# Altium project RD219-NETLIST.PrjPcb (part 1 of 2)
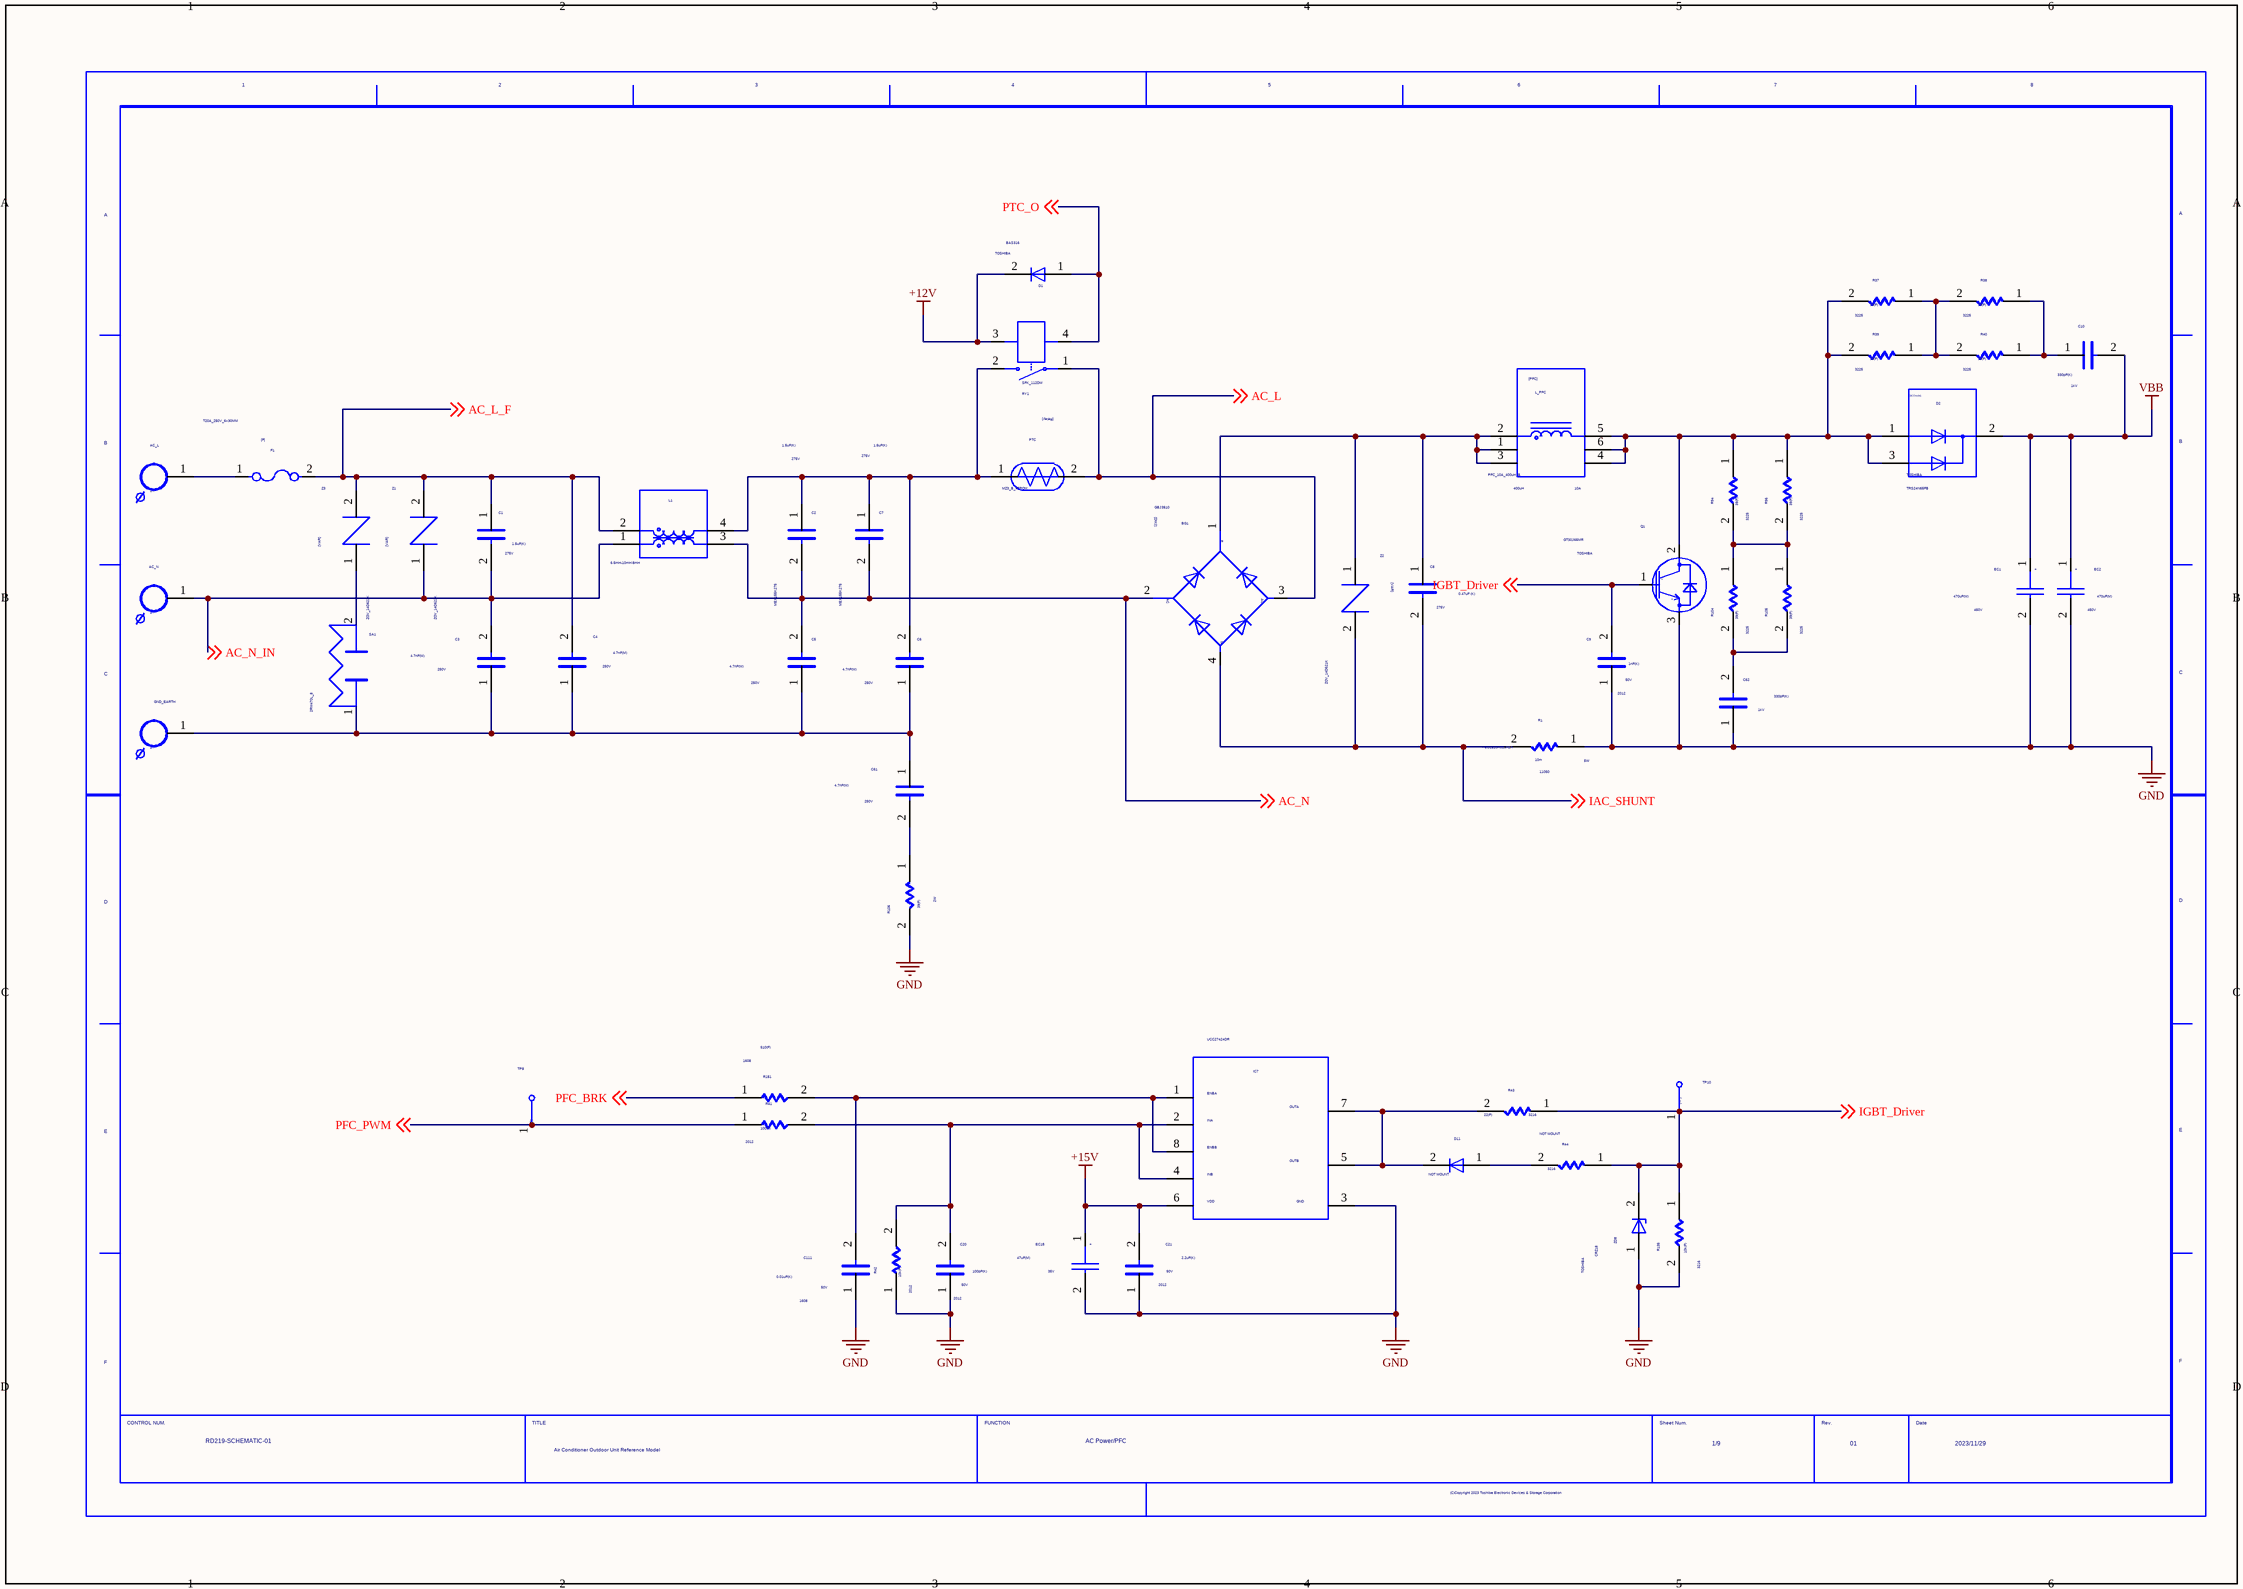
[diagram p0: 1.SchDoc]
9 sheets, 407 parts. Net scope: global (net labels, ports and power ports of the same name join across sheets).
Sheets:
  1.SchDoc
  2.SchDoc
  3.SchDoc
  4.SchDoc
  5.SchDoc
  6.SchDoc
  7.SchDoc
  8.SchDoc
  9.SchDoc

## Sheet 1.SchDoc
size 420 x 297 mm

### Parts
(Parts that share a designator on the sheet are numbered #1, #2 ... from top to bottom, then left to right.)
AC_L  TB1Y  (value not drawn)
AC_N  TB1Y  (value not drawn)
BG1  VAL1: GBJ3510  (hidden comment: DMJ)
C1  VAL2: 275V  VAL1: 1.5uF(K)  (hidden comment: C)
C2  VAL2: 275V  VAL1: 1.5uF(K)  VAL3: MEX155K275  (hidden comment: C)
C3  VAL2: 250V  VAL1: 4.7nF(M)  (hidden comment: C)
C4  VAL2: 250V  VAL1: 4.7nF(M)  (hidden comment: C)
C5  VAL2: 250V  VAL1: 4.7nF(M)  (hidden comment: C)
C6  VAL2: 250V  VAL1: 4.7nF(M)  (hidden comment: C)
C7  VAL2: 275V  VAL1: 1.5uF(K)  VAL3: MEX155K275  (hidden comment: C)
C8  VAL2: 275V  VAL1: 0.47uF (K)  (hidden comment: C)
C9  SIZECODESMD: 2012  VAL2: 50V  VAL1: 1nF(K)  (hidden comment: C)
C10  VAL2: 1kV  VAL1: 330pF(K)  (hidden comment: C)
C20  SIZECODESMD: 2012  VAL2: 50V  VAL1: 100pF(K)  (hidden comment: C)
C21  SIZECODESMD: 2012  VAL2: 50V  VAL1: 2.2uF(K)  (hidden comment: C)
C61  VAL2: 250V  VAL1: 4.7nF(M)  (hidden comment: C)
C62  VAL2: 1kV  VAL1: 330pF(K)  (hidden comment: C)
C111  SIZECODESMD: 1608  VAL2: 50V  VAL1: 0.01uF(K)  (hidden comment: C)
D1  USERCOMPTEXT3: TOSHIBA  VAL3: BAS316  (hidden comment: D_CUSTOM)
D2  USERCOMPTEXT3: TOSHIBA  VAL3: TRS24N65FB  (hidden comment: TRS24N)
D11  NOTMOUNT: NOT MOUNT  (hidden comment: D_CUSTOM)
EC1  VAL2: 450V  VAL1: 470uF(M)  (hidden comment: EC)
EC2  VAL2: 450V  VAL1: 470uF(M)  (hidden comment: EC)
EC15  VAL2: 35V  VAL1: 47uF(M)  (hidden comment: EC)
F1  COMP: T20A_250V_6x30MM  (hidden comment: F)
GND_EARTH  TB1Y  (value not drawn)
IC7  VAL1: UCC27424DR  (hidden comment: UCC27424)
L1  COMPCOMMENT: 6.5mH-10mH:8mH  (hidden comment: L2Y)
L_PFC  VAL3: PFC_10A_400uH_B  VAL2: 10A  VAL1: 400uH  (hidden comment: PFC)
PTC  VAL1: MZ3_B_47ROM  (hidden comment: PTC)
Q1  USERCOMPTEXT3: TOSHIBA  VAL3: GT30J65MR  (hidden comment: IGBT)
R1  SIZECODESMD: 11050  VAL3: FCSL110R010FER  VAL2: 5W  VAL1: 10m  (hidden comment: R)
R37  SIZECODESMD: 3225  VAL1: 39(F)  (hidden comment: R)
R38  SIZECODESMD: 3225  VAL1: 39(F)  (hidden comment: R)
R39  SIZECODESMD: 3225  VAL1: 39(F)  (hidden comment: R)
R40  SIZECODESMD: 3225  VAL1: 39(F)  (hidden comment: R)
R41  SIZECODESMD: 2012  VAL1: 100(F)  (hidden comment: R)
R42  SIZECODESMD: 2012  VAL1: 10k(F)  (hidden comment: R)
R43  SIZECODESMD: 3216  VAL1: 22(F)  (hidden comment: R)
R44  SIZECODESMD: 3216  NOTMOUNT: NOT MOUNT  (hidden comment: R)
R94  SIZECODESMD: 3225  VAL1: 39(F)  (hidden comment: R)
R96  SIZECODESMD: 3225  VAL1: 39(F)  (hidden comment: R)
R104  SIZECODESMD: 3225  VAL1: 39(F)  (hidden comment: R)
R105  SIZECODESMD: 3225  VAL1: 39(F)  (hidden comment: R)
R106  VAL2: 2W  VAL1: 39(F)  (hidden comment: R)
R135  SIZECODESMD: 3216  VAL1: 10k(F)  (hidden comment: R)
R151  SIZECODESMD: 1608  VAL1: 510(F)  (hidden comment: R)
RY1  VAL1: SFK_112DM  (hidden comment: SFK-112)
SA1  COMP: 2RM470L_8  (hidden comment: GDT)
TP8  TP  (value not drawn)
TP10  TP  (value not drawn)
U?#1  DATE: 2023/11/29  TITLE: Air Conditioner Outdoor Unit / Reference Model  SHEETNUMBER: 1/9  FUNCTION: AC Power/PFC  REVISION: 01  DRAWINGNUMBER: RD219-SCHEMATIC-01  (hidden comment: WAKU_DEF100)
Z1  VAL3: ZOV_14D621K  (hidden comment: VAR)
Z2  VAL3: ZOV_14D621K  (hidden comment: VAR)
Z3  VAL3: ZOV_14D621K  (hidden comment: VAR)
ZD8  USERCOMPTEXT3: TOSHIBA  VAL1: CRZ18  (hidden comment: ZD)

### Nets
+12V: D1.2 RY1.3
+15V: C21.2 EC15.1 IC7.6
GND: C9.1 C20.1 C21.1 C62.1 C111.1 EC1.2 EC2.2 EC15.2 IC7.3 Q1.3 R1.1 R42.1 R106.2 R135.2 ZD8.1(A)
VBB: C10.2 D2.2 EC1.1 EC2.1
AC_L: BG1.3 PTC.2 RY1.1 ; off-sheet AC_L
AC_L_F: C1.1 C4.2 F1.2 L1.2 Z1.2 Z3.2 ; off-sheet AC_L_F
AC_N: BG1.2 C2.2 C5.2 C7.2 L1.3 ; off-sheet AC_N
AC_N_IN: AC_N.1 C1.2 C3.2 L1.1 Z1.1 ; off-sheet AC_N_IN
IAC_SHUNT: BG1.4 C8.2 R1.2 Z2.2 ; off-sheet IAC_SHUNT
IGBT_Driver: C9.2 Q1.1 R43.1 R44.1 R135.1 TP10.1 ZD8.2(C) ; off-sheet IGBT_Driver
NetAC_L_1: AC_L.1 F1.1
NetBG1_1: BG1.1 C8.1 L_PFC.1 L_PFC.2 L_PFC.3 Z2.1
NetC2_1: C2.1 C6.2 C7.1 L1.4 PTC.1 RY1.2
NetC3_1: C3.1 C4.1 C5.1 C6.1 C61.1 GND_EARTH.1 SA1.1
NetC10_1: C10.1 R38.1 R40.1
NetC20_2: C20.2 IC7.2 IC7.4 R41.2 R42.2
NetC61_2: C61.2 R106.1
NetC62_2: C62.2 R104.2 R105.2
NetC111_2: C111.2 IC7.1 IC7.8 R151.2
NetD2_1: D2.1 D2.3 L_PFC.4 L_PFC.5 L_PFC.6 Q1.2 R37.2 R39.2 R94.1 R96.1
NetD11_1: D11.1 R44.2
NetD11_2: D11.2 IC7.5 IC7.7 R43.2
NetR37_1: R37.1 R38.2 R39.1 R40.2
NetR94_2: R94.2 R96.2 R104.1 R105.1
NetSA1_2: SA1.2 Z3.1
PFC_BRK: R151.1 ; off-sheet PFC_BRK
PFC_PWM: R41.1 TP8.1 ; off-sheet PFC_PWM
PTC_O: D1.1 RY1.4 ; off-sheet PTC_O

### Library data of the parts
AC_L = TB1Y: SAVEAREA0: -4386,-117,16897,10471; TIME: 15:17:35; UPDATEUSER: w20165dm; SAVECOUNT: 1; OriginalSymbolOrigin: (0,7620); VAL3: AC-L; COMP: PAD
AC_N = TB1Y: SAVEAREA0: -4386,-117,16897,10471; TIME: 15:17:35; UPDATEUSER: w20165dm; SAVECOUNT: 1; OriginalSymbolOrigin: (0,7620); VAL3: AC-N; COMP: PAD
BG1 = DMJ: SAVECOUNT: 8; SAVEAREA0: -14111,-292,39054,26173; TIME: 10:09:47; UPDATEUSER: 19990028; UPDATETIME: 09:28:12; OriginalSymbolOrigin: (0,25400)
C1 = C_Dup1: OriginalSymbolOrigin: (2540,7620); VAL3: MEX155K275
C2 C7 = C_Dup1: OriginalSymbolOrigin: (2540,7620)
C3-C6 C61 = C_Dup1: OriginalSymbolOrigin: (2540,7620); VAL3: DE1E3KX472MA4BN01F; COMP: JN472M
C8 = C_Dup1: OriginalSymbolOrigin: (2540,7620); COMPCOMMENT: MKP474/275VAC; VAL3: MEX474K275
C9 = C_Dup1: OriginalSymbolOrigin: (2540,7620); VAL3: AC0805KRX7R9BB102
C10 C62 = C_Dup1: OriginalSymbolOrigin: (2540,7620); VAL3: CK45-B3AD331KYGNA; COMP: 331_1KV
C20 = C: OriginalSymbolOrigin: (2540,7620); VAL3: AC0805KRX7R9BB101
C21 = C: OriginalSymbolOrigin: (2540,7620); COMP: AC0805KRX7R9BB225
C111 = C: OriginalSymbolOrigin: (2540,7620); VAL3: GCM188R71H103KA37D
D1 = D_CUSTOM: SAVEAREA0: -1668,-97,14265,7829; SAVECOUNT: 4; TIME: 14:49:55; UPDATEUSER: w20165dm; UPDATETIME: 16:47:49; OriginalSymbolOrigin: (5080,5080)
D2 = TRS24N: SAVEAREA0: -10023,-235,32546,20943; TIME: 17:15:17; UPDATEUSER: w20165dm; SAVECOUNT: 1; OriginalSymbolOrigin: (5080,20320)
D11 = D_CUSTOM: SAVEAREA0: -1668,-97,14265,7829; SAVECOUNT: 4; TIME: 14:49:55; UPDATEUSER: w20165dm; UPDATETIME: 16:47:49; OriginalSymbolOrigin: (5080,5080); COMP: 1N4148
EC1 EC2 = EC: SAVEAREA0: -1432,-1528,20311,14389; SAVECOUNT: 53; TIME: 15:02:55; UPDATEUSER: w20165dm; UPDATETIME: 16:35:05; OriginalSymbolOrigin: (2540,10160); VAL3: 450VXG470MEFCSN35X45
EC15 = EC: SAVEAREA0: -1432,-1528,20311,14389; SAVECOUNT: 53; TIME: 15:02:55; UPDATEUSER: w20165dm; UPDATETIME: 16:35:05; OriginalSymbolOrigin: (2540,10160); VAL3: CS1V470M_CRE54
F1 = F: OriginalSymbolOrigin: (2540,5080); VAL2: 250V; VAL1: 20A
GND_EARTH = TB1Y: SAVEAREA0: -4386,-117,16897,10471; TIME: 15:17:35; UPDATEUSER: w20165dm; SAVECOUNT: 1; OriginalSymbolOrigin: (0,7620); VAL3: GND_EARTH; COMP: PAD
IC7 = UCC27424: SAVEAREA0: -18701,-404,54363,35945; TIME: 14:53:37; UPDATEUSER: w20165dm; UPDATETIME: 17:37:13; SAVECOUNT: 7; OriginalSymbolOrigin: (5080,33020)
L1 = L2Y: SAVEAREA0: -7346,-206,29901,18324; TIME: 15:13:45; UPDATEUSER: w20165dm; SAVECOUNT: 1; OriginalSymbolOrigin: (5080,15240); VAL2: 20A; VAL1: 6.5mH-10mH; COMP: INDUCTOR_IRON_DOT
L_PFC = PFC: SAVEAREA0: -15388,-294,37822,26178; TIME: 13:55:27; UPDATEUSER: w20165dm; SAVECOUNT: 1; OriginalSymbolOrigin: (5080,22860); COMPCOMMENT: Inductor Iron Dot
PTC = PTC: TIME: 17:09:47; UPDATEUSER: w20165dm; UPDATETIME: 17:16:29; SAVECOUNT: 2; SAVEAREA0: -4525,-147,22079,13088; OriginalSymbolOrigin: (5080,7620)
Q1 = IGBT: TIME: 09:39:04; UPDATEUSER: w20165dm; UPDATETIME: 16:59:47; SAVECOUNT: 10; SAVEAREA0: -8472,-176,23454,15707; OriginalSymbolOrigin: (2540,12700)
R1 = R_Dup1: OriginalSymbolOrigin: (5080,5080)
R37 R38 R40 = R_Dup1: OriginalSymbolOrigin: (5080,5080); VAL3: AC1210FR-0739RL; VAL2: 500mW; COMP: AC1210FR_0739RL
R39 = R_Dup1: OriginalSymbolOrigin: (5080,5080); VAL2: 500mW; COMP: AC1210FR_0739RL; VAL3: AC1210FR-0739RL
R41 = R: OriginalSymbolOrigin: (5080,5080); VAL3: AC0805FR-07100RL; VAL2: 125mW; COMP: AC0805FR_07100RL
R42 = R: OriginalSymbolOrigin: (5080,5080); VAL3: AC0805FR-0710KL; VAL2: 125mW; COMP: AC0805FR_0710KL
R43 = R: OriginalSymbolOrigin: (5080,5080); VAL2: 250mW; VAL3: AC1206FR-0722RL; COMP: AC1206FR_0722RL
R44 = R: OriginalSymbolOrigin: (5080,5080); COMP: SMT_1206_R
R94 R104 = R_Dup1: OriginalSymbolOrigin: (5080,5080); VAL2: 500mW; VAL3: AC1210FR_0739RL
R96 R105 = R_Dup1: OriginalSymbolOrigin: (5080,5080); VAL3: AC1210FR_0739RL; VAL2: 500mW
R106 = R_Dup1: OriginalSymbolOrigin: (5080,5080); VAL3: MFR2WSFTE73_39R
R135 = R: OriginalSymbolOrigin: (5080,5080); VAL3: AC1206FR_0710KL; VAL2: 250mW
R151 = R: OriginalSymbolOrigin: (5080,5080); VAL3: AC0603FR_07510RL; VAL2: 100mW
RY1 = SFK-112: SAVEAREA0: -13231,-231,28521,20540; TIME: 14:06:16; UPDATEUSER: w20165dm; UPDATETIME: 17:57:42; SAVECOUNT: 24; OriginalSymbolOrigin: (2540,12700)
SA1 = GDT: TIME: 16:28:26; UPDATEUSER: w20165dm; UPDATETIME: 16:32:17; SAVECOUNT: 3; SAVEAREA0: -9109,-176,22817,15707; OriginalSymbolOrigin: (0,15240); VAL3: 2RM470L-8; VAL2: 10kA; VAL1: 470V
TP8 TP10 = TP_Dup1: TIME: 16:12:21; UPDATEUSER: fukuda-y; UPDATETIME: 16:18:11; SAVECOUNT: 2; SAVEAREA0: -242,-92,12810,7836; OriginalSymbolOrigin: (0,7620); VAL3: ZXD
U?#1 = WAKU_DEF100: PLOTTIME: HH:MM; SAVEAREA0: -45080,-4508,463680,304612; TIME: 17:28:05; UPDATEUSER: sptcae13; UPDATETIME: 08:19:30; SAVECOUNT: 8; OriginalSymbolOrigin: (10160,284480)
Z1 Z3 = VAR: SAVEAREA0: -418,-1801,15408,7141; SAVECOUNT: 5; OriginalSymbolOrigin: (5080,5080)
Z2 = VAR: SAVEAREA0: -418,-1801,15408,7141; SAVECOUNT: 5; OriginalSymbolOrigin: (5080,5080); COMP: ZOV_14D621K_18MM
ZD8 = ZD: SAVEAREA0: -4071,-115,16804,10270; TIME: 09:43:08; UPDATEUSER: w20165dm; UPDATETIME: 16:32:57; SAVECOUNT: 6; OriginalSymbolOrigin: (5080,5080)

## Sheet 2.SchDoc
size 420 x 297 mm
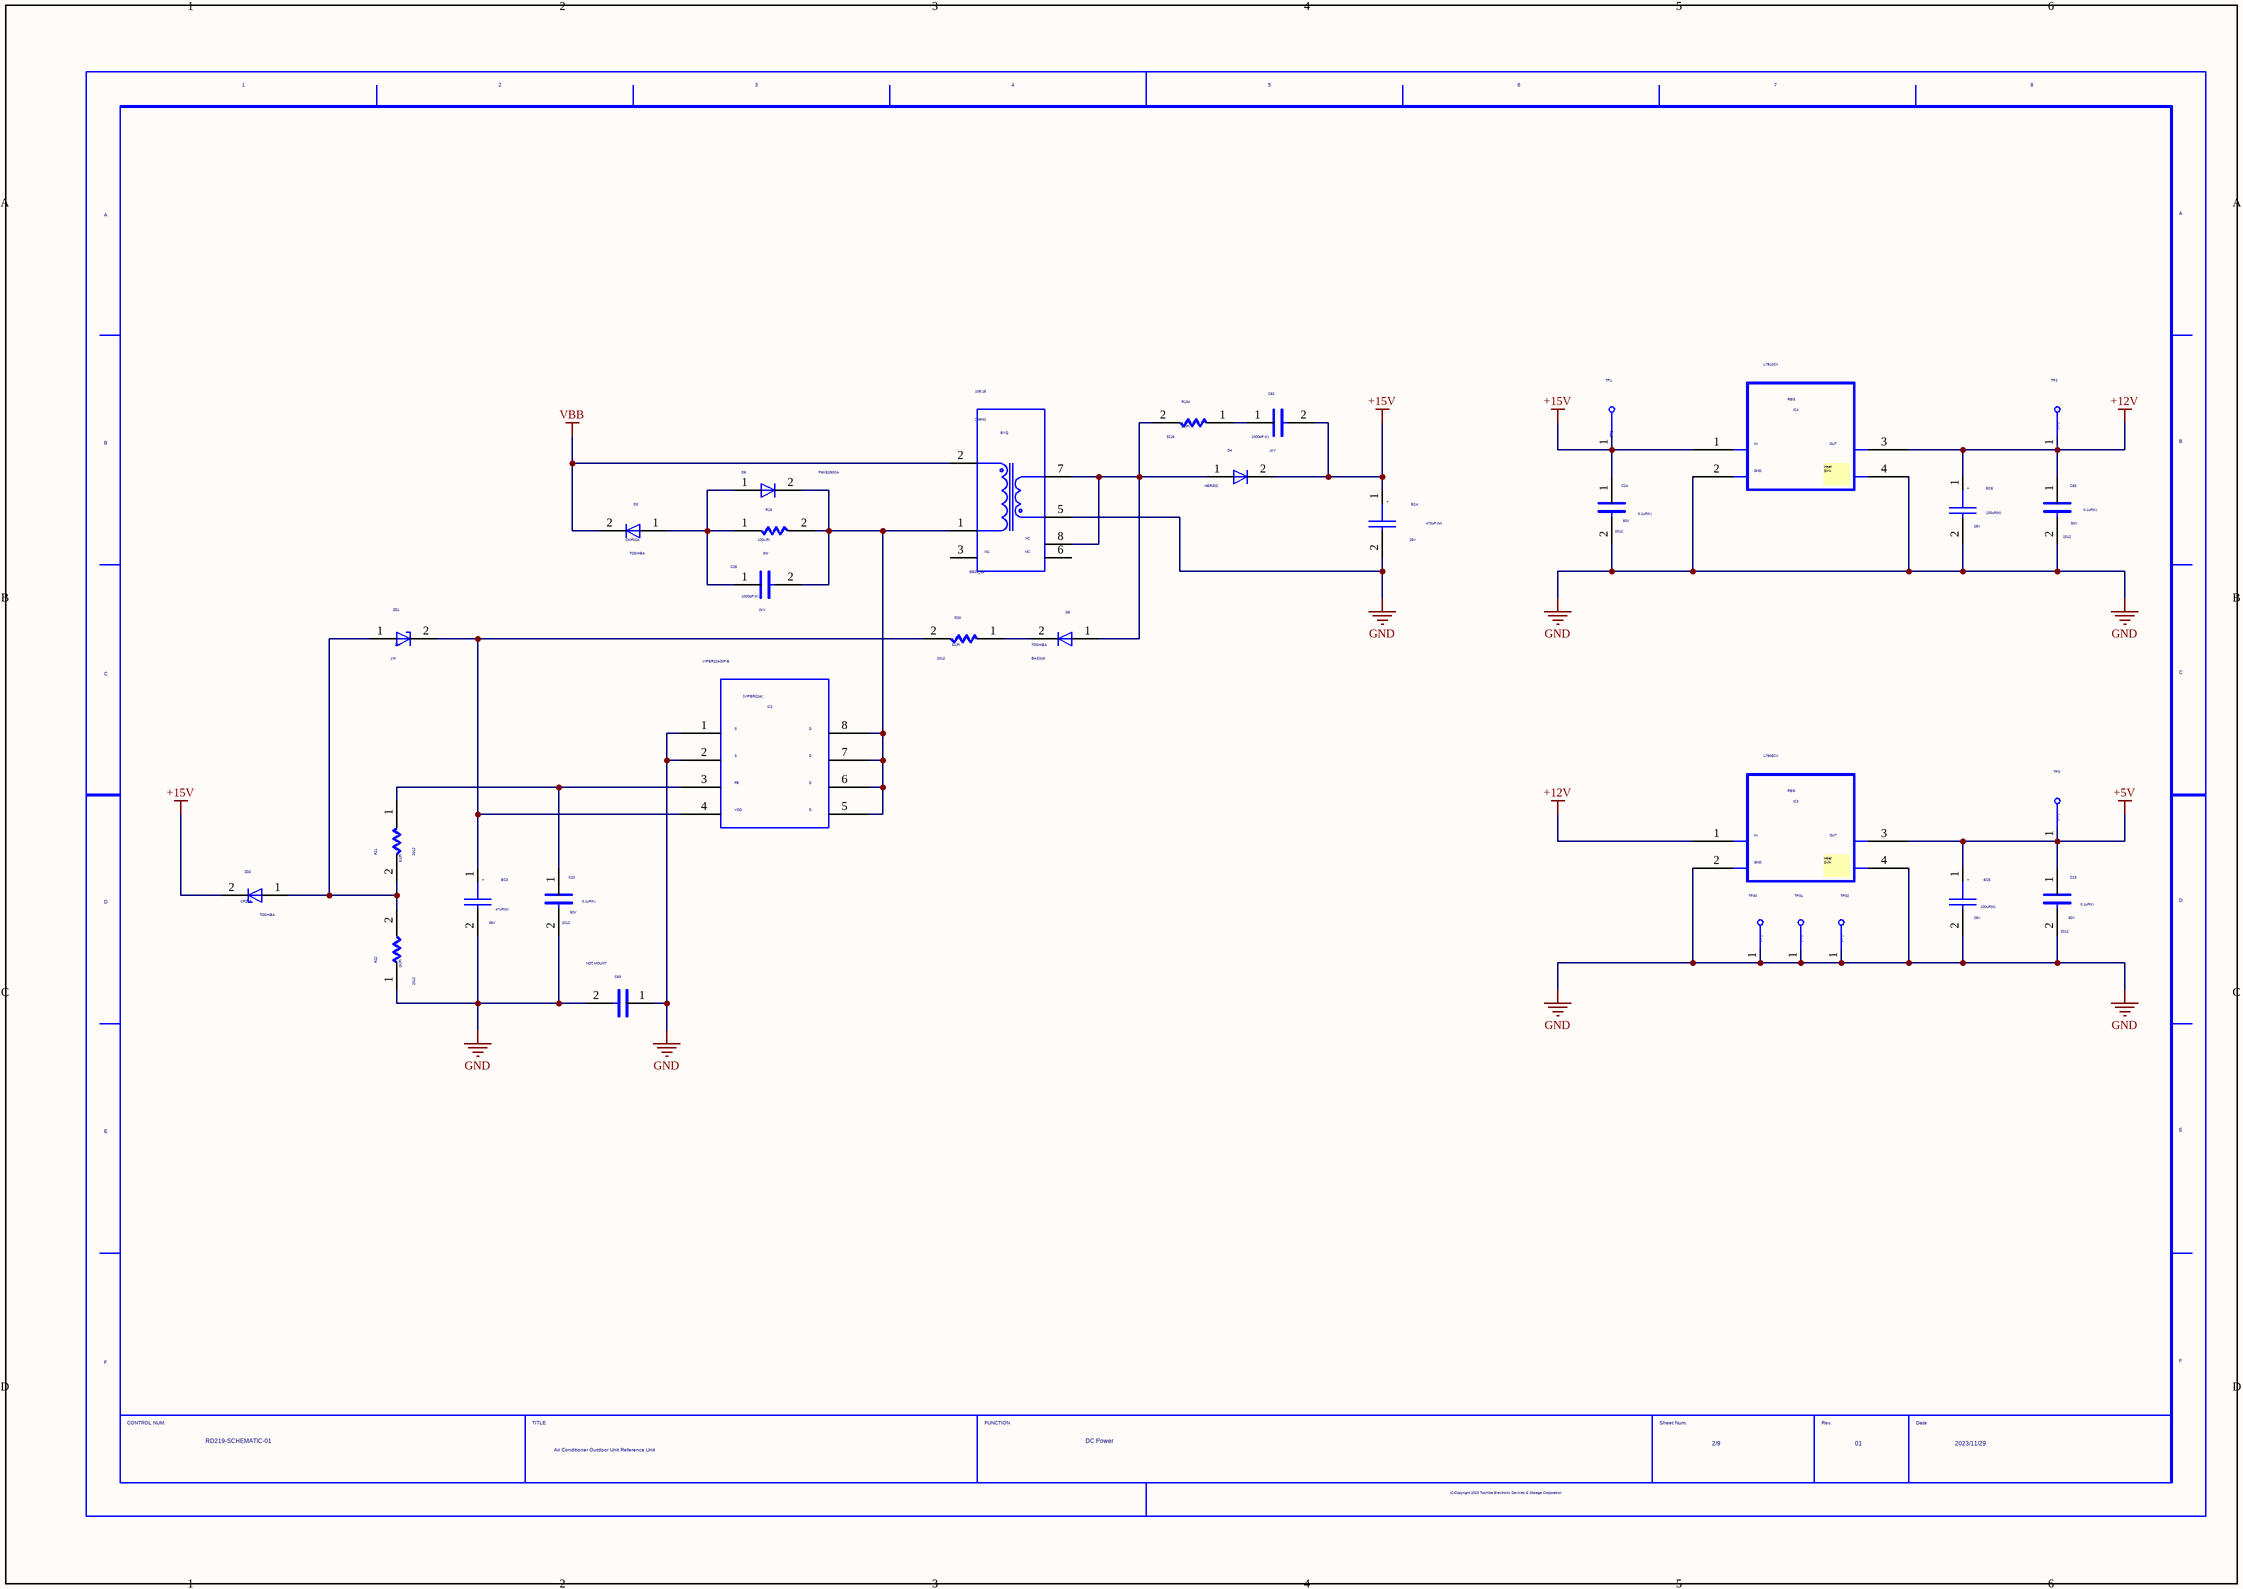
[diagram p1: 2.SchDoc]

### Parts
(Parts that share a designator on the sheet are numbered #1, #2 ... from top to bottom, then left to right.)
BYQ  VAL3: EE25_22  VAL1: 105:15  (hidden comment: EE25-22)
C22  SIZECODESMD: 2012  VAL2: 50V  VAL1: 0.1uF(K)  (hidden comment: C)
C23  SIZECODESMD: 2012  VAL2: 50V  VAL1: 0.1uF(K)  (hidden comment: C)
C24  SIZECODESMD: 2012  VAL2: 50V  VAL1: 0.1uF(K)  (hidden comment: C)
C25  VAL2: 2kV  VAL1: 1000pF (K)  (hidden comment: C)
C63  NOTMOUNT: NOT MOUNT  (hidden comment: C)
C82  VAL2: 1kV  VAL1: 1000pF (K)  (hidden comment: C)
C83  SIZECODESMD: 2012  VAL2: 50V  VAL1: 0.1uF(K)  (hidden comment: C)
D3  USERCOMPTEXT3: TOSHIBA  VAL3: CMF02A  (hidden comment: D_CUSTOM)
D4  VAL3: HER302  (hidden comment: D_CUSTOM)
D5  USERCOMPTEXT3: TOSHIBA  VAL3: BAS316  (hidden comment: D_CUSTOM)
D6  VAL3: P6KE250CA  (hidden comment: D_CUSTOM)
EC3  VAL2: 35V  VAL1: 47uF(M)  (hidden comment: EC)
EC4  VAL2: 25V  VAL1: 470uF (M)  (hidden comment: EC)
EC5  VAL2: 25V  VAL1: 100uF(M)  (hidden comment: EC)
EC6  VAL2: 25V  VAL1: 100uF(M)  (hidden comment: EC)
IC2  VAL1: VIPER22ADIP-E  (hidden comment: VIPER22A)
IC3  VAL3: L7805CV  (hidden comment: REG)
IC4  VAL3: L7812CV  (hidden comment: REG)
R19  VAL2: 3W  VAL1: 100k(F)  (hidden comment: R)
R20  SIZECODESMD: 2012  VAL1: 51(F)  (hidden comment: R)
R21  SIZECODESMD: 2012  VAL1: 51(F)  (hidden comment: R)
R22  SIZECODESMD: 2012  VAL1: 2k(F)  (hidden comment: R)
R134  SIZECODESMD: 3216  VAL1: 22(F)  (hidden comment: R)
TP1  TP  (value not drawn)
TP2  TP  (value not drawn)
TP3  TP  (value not drawn)
TP30  TP  (value not drawn)
TP31  TP  (value not drawn)
TP32  TP  (value not drawn)
U?#2  DATE: 2023/11/29  TITLE: Air Conditioner Outdoor Unit / Reference Unit  SHEETNUMBER: 2/9  FUNCTION: DC Power  REVISION: 01  DRAWINGNUMBER: RD219-SCHEMATIC-01  (hidden comment: WAKU_DEF100)
ZD1  VAL2: 1W  VAL1: 24V  (hidden comment: ZD)
ZD2  USERCOMPTEXT3: TOSHIBA  VAL1: CRZ15  (hidden comment: ZD)

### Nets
+5V: C23.1 EC5.1 IC3.3 TP3.1
+12V: C83.1 EC6.1 IC3.1 IC4.3 TP2.1
+15V: C24.1 C82.2 D4.2 EC4.1 IC4.1 TP1.1 ZD2.2(C)
GND: BYQ.5 C22.2 C23.2 C24.2 C63.1 C63.2 C83.2 EC3.2 EC4.2 EC5.2 EC6.2 IC2.1 IC2.2 IC3.2 IC3.4 IC4.2 IC4.4 R22.1 TP30.1 TP31.1 TP32.1
VBB: BYQ.2 D3.2
NetBYQ_1: BYQ.1 C25.2 D6.2 IC2.5 IC2.6 IC2.7 IC2.8 R19.2
NetBYQ_7: BYQ.7 BYQ.8 D4.1 D5.1 R134.2
NetC22_1: C22.1 IC2.3 R21.1
NetC25_1: C25.1 D3.1 D6.1 R19.1
NetC82_1: C82.1 R134.1
NetD5_2: D5.2 R20.1
NetEC3_1: EC3.1 IC2.4 R20.2 ZD1.2(C)
NetR21_2: R21.2 R22.2 ZD1.1(A) ZD2.1(A)

Not connected (* = marked no-connect by the designer): BYQ 3 6

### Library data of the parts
BYQ = EE25-22: TIME: 15:54:32; UPDATEUSER: w20165dm; UPDATETIME: 16:30:52; SAVECOUNT: 7; SAVEAREA0: -19178,-336,41553,33915; OriginalSymbolOrigin: (5080,30480)
C22-C24 C83 = C: OriginalSymbolOrigin: (2540,7620); VAL3: AC0805KRX7R9BB104
C25 = C: OriginalSymbolOrigin: (2540,7620); VAL3: CK45-B3DD102KYNNA; COMP: 102_2KV
C63 = C: OriginalSymbolOrigin: (2540,7620); COMP: C7.5MM
C82 = C: OriginalSymbolOrigin: (2540,7620); VAL3: CK45-B3AD102KYVNA; COMP: 102_1KV
D3-D6 = D_CUSTOM: as D1 on sheet 1
EC3 = EC: SAVEAREA0: -1432,-1528,20311,14389; SAVECOUNT: 53; TIME: 15:02:55; UPDATEUSER: w20165dm; UPDATETIME: 16:35:05; OriginalSymbolOrigin: (2540,10160); VAL3: ESY476M035AE3AA; COMP: 35V47uF_6.3X7
EC4 = EC: SAVEAREA0: -1432,-1528,20311,14389; SAVECOUNT: 53; TIME: 15:02:55; UPDATEUSER: w20165dm; UPDATETIME: 16:35:05; OriginalSymbolOrigin: (2540,10160); VAL3: ESH477M025AG4AA
EC5 EC6 = EC: SAVEAREA0: -1432,-1528,20311,14389; SAVECOUNT: 53; TIME: 15:02:55; UPDATEUSER: w20165dm; UPDATETIME: 16:35:05; OriginalSymbolOrigin: (2540,10160); VAL3: ESK107M025AE3AA; COMP: 25V100uF_6.3X11
IC2 = VIPER22A: SAVEAREA0: -16087,-375,51758,33378; SAVECOUNT: 16; TIME: 11:13:15; UPDATEUSER: w20165dm; UPDATETIME: 13:40:21; OriginalSymbolOrigin: (7620,30480); COMP: VIPER22ADIP_E
IC3 IC4 = REG: SAVEAREA0: -5753,-289,46434,25674; SAVECOUNT: 4; TIME: 17:36:06; UPDATEUSER: w20165dm; UPDATETIME: 17:45:44; OriginalSymbolOrigin: (7620,22860)
R19 = R: OriginalSymbolOrigin: (5080,5080); VAL3: MF3WS-100KOhm; COMP: MF3WS_100K
R20 R21 = R: OriginalSymbolOrigin: (5080,5080); VAL3: AC0805FR-0751RL; VAL2: 125mW; COMP: AC0805FR_0751RL
R22 = R: OriginalSymbolOrigin: (5080,5080); VAL2: 125mW; VAL3: AC0805FR-072KL; COMP: AC0805FR_072KL
R134 = R: OriginalSymbolOrigin: (5080,5080); VAL2: 250mW; VAL3: AC1206FR_0722RL
TP1 = TP_Dup1: TIME: 16:12:21; UPDATEUSER: fukuda-y; UPDATETIME: 16:18:11; SAVECOUNT: 2; SAVEAREA0: -242,-92,12810,7836; OriginalSymbolOrigin: (0,7620); VAL3: ZXD; COMPCOMMENT: +15V
TP2 = TP_Dup1: TIME: 16:12:21; UPDATEUSER: fukuda-y; UPDATETIME: 16:18:11; SAVECOUNT: 2; SAVEAREA0: -242,-92,12810,7836; OriginalSymbolOrigin: (0,7620); VAL3: ZXD; COMPCOMMENT: +12V
TP3 = TP_Dup1: TIME: 16:12:21; UPDATEUSER: fukuda-y; UPDATETIME: 16:18:11; SAVECOUNT: 2; SAVEAREA0: -242,-92,12810,7836; OriginalSymbolOrigin: (0,7620); VAL3: ZXD; COMPCOMMENT: +5V
TP30-TP32 = TP_Dup1: TIME: 16:12:21; UPDATEUSER: fukuda-y; UPDATETIME: 16:18:11; SAVECOUNT: 2; SAVEAREA0: -242,-92,12810,7836; OriginalSymbolOrigin: (0,7620); VAL3: ZXD; COMPCOMMENT: GND
U?#2 = WAKU_DEF100: PLOTTIME: HH:MM; SAVEAREA0: -45080,-4508,463680,304612; TIME: 17:44:02; UPDATEUSER: sptcae13; UPDATETIME: 08:19:30; SAVECOUNT: 8; OriginalSymbolOrigin: (10160,284480)
ZD1 = ZD: SAVEAREA0: -4071,-115,16804,10270; TIME: 09:43:08; UPDATEUSER: w20165dm; UPDATETIME: 16:32:57; SAVECOUNT: 6; OriginalSymbolOrigin: (5080,5080); VAL3: ZM4749A
ZD2 = ZD: as ZD8 on sheet 1

## Sheet 3.SchDoc
size 420 x 297 mm
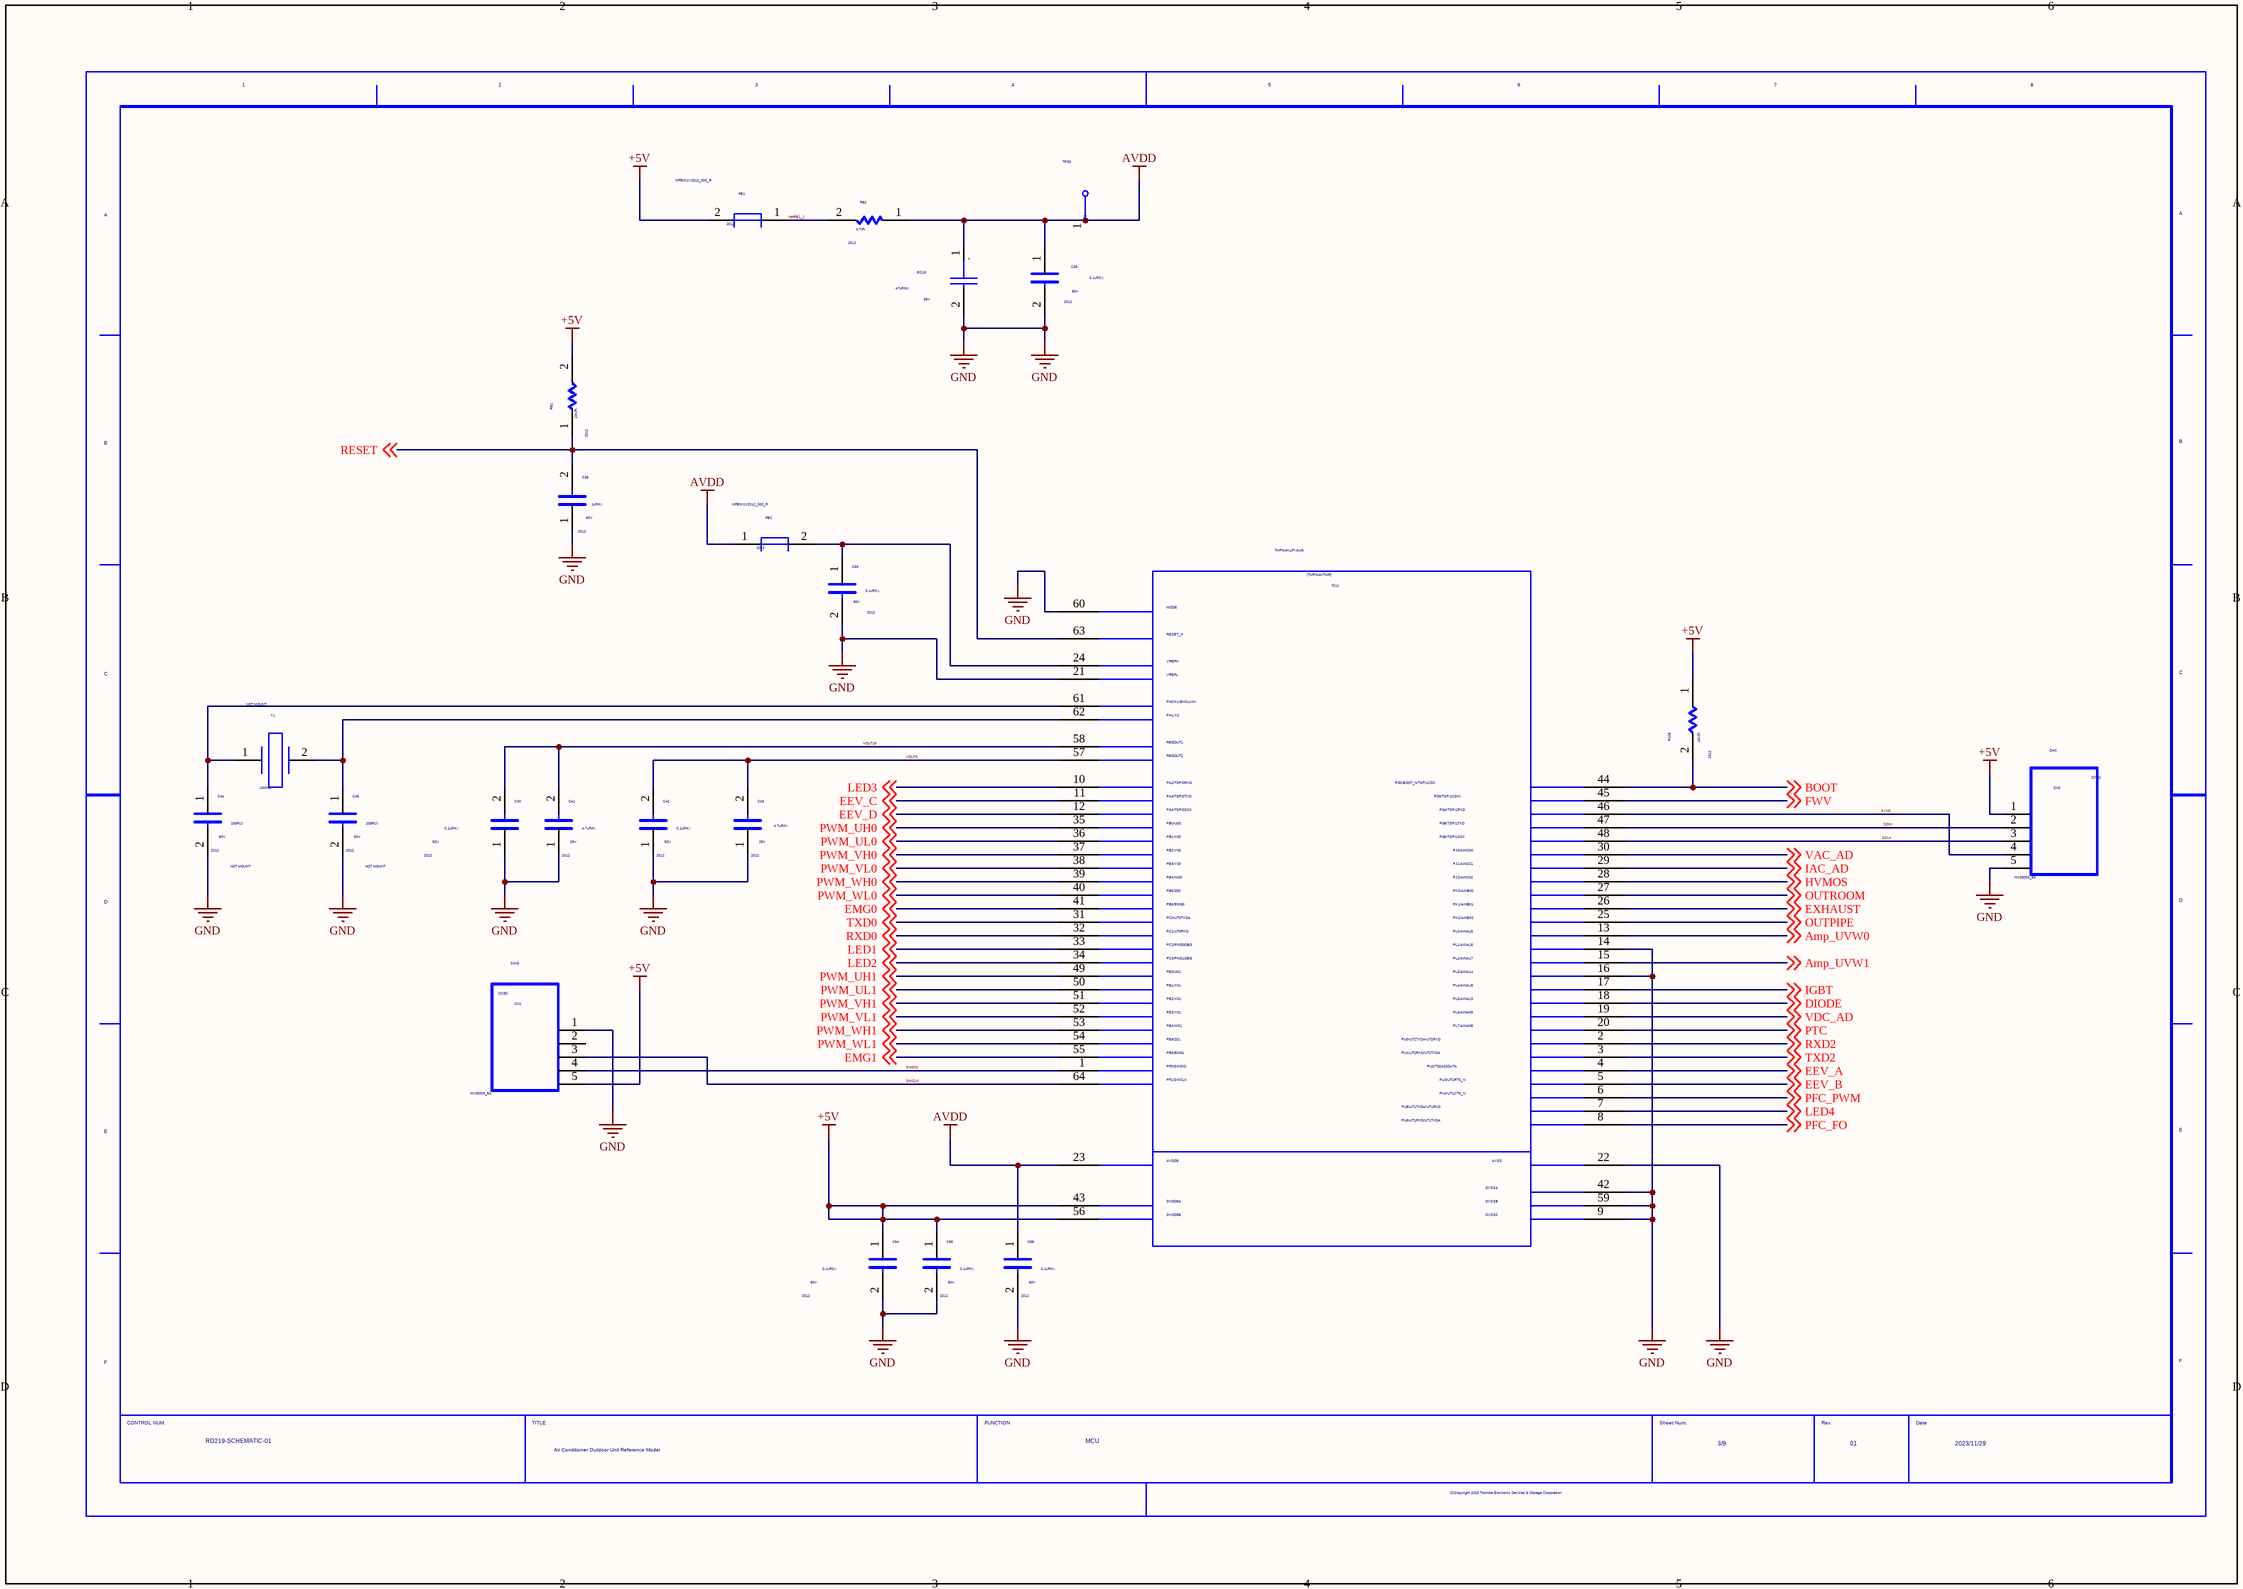
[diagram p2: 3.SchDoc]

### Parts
(Parts that share a designator on the sheet are numbered #1, #2 ... from top to bottom, then left to right.)
C38  SIZECODESMD: 2012  VAL2: 50V  VAL1: 1uF(K)  (hidden comment: C)
C39  SIZECODESMD: 2012  VAL2: 50V  VAL1: 0.1uF(K)  (hidden comment: C)
C40  SIZECODESMD: 2012  VAL2: 50V  VAL1: 0.1uF(K)  (hidden comment: C)
C41  SIZECODESMD: 2012  VAL2: 25V  VAL1: 4.7uF(K)  (hidden comment: C)
C42  SIZECODESMD: 2012  VAL2: 50V  VAL1: 0.1uF(K)  (hidden comment: C)
C43  SIZECODESMD: 2012  VAL2: 25V  VAL1: 4.7uF(K)  (hidden comment: C)
C44  NOTMOUNT: NOT MOUNT  SIZECODESMD: 2012  VAL2: 50V  VAL1: 20pF(J)  (hidden comment: C)
C45  NOTMOUNT: NOT MOUNT  SIZECODESMD: 2012  VAL2: 50V  VAL1: 20pF(J)  (hidden comment: C)
C64  SIZECODESMD: 2012  VAL2: 50V  VAL1: 0.1uF(K)  (hidden comment: C)
C65  SIZECODESMD: 2012  VAL2: 50V  VAL1: 0.1uF(K)  (hidden comment: C)
C98  SIZECODESMD: 2012  VAL2: 50V  VAL1: 0.1uF(K)  (hidden comment: C)
C99  SIZECODESMD: 2012  VAL2: 50V  VAL1: 0.1uF(K)  (hidden comment: C)
CN1  VAL3: HX25003_5A  COMPCOMMENT: SWD  (hidden comment: CN5)
CN2  VAL3: HX25003_5A  COMPCOMMENT: DAC  (hidden comment: CN5)
EC18  VAL2: 35V  VAL1: 47uF(M)  (hidden comment: EC)
FB1  SIZECODESMD: 2012  VAL3: MFBW1V2012_000_R  (hidden comment: FL08A)
FB2  SIZECODESMD: 2012  VAL3: MFBW1V2012_000_R  (hidden comment: FL08A)
IC11  TMPM4KLFYAUG
R81  SIZECODESMD: 2012  VAL1: 10k(F)  (hidden comment: R)
R82  SIZECODESMD: 2012  VAL1: 4.7(F)  (hidden comment: R)
R108  SIZECODESMD: 2012  VAL1: 10k(F)  (hidden comment: R)
TP33  TP  (value not drawn)
U?#3  DATE: 2023/11/29  TITLE: Air Conditioner Outdoor Unit / Reference Model  DRAWINGNUMBER: RD219-SCHEMATIC-01  SHEETNUMBER: 3/9  REVISION: 01  FUNCTION: MCU  (hidden comment: WAKU_DEF100)
Y1  NOTMOUNT: NOT MOUNT  VAL1: 10MHz  (hidden comment: X)

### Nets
+5V: C64.1 C65.1 CN1.5 CN2.1 FB1.2 IC11.43 IC11.56 R81.2 R108.1
AVDD: C39.1 C98.1 EC18.1 FB2.1 IC11.23 R82.1 TP33.1
GND: C38.1 C39.2 C40.1 C41.1 C42.1 C43.1 C44.2 C45.2 C64.2 C65.2 C98.2 C99.2 CN1.1 CN2.5 EC18.2 IC11.9 IC11.14 IC11.16 IC11.21 IC11.22 IC11.42 IC11.59 IC11.60
Amp_UVW0: IC11.13 ; off-sheet Amp_UVW0
Amp_UVW1: IC11.15 ; off-sheet Amp_UVW1
BOOT: IC11.44 R108.2 ; off-sheet BOOT
DIODE: IC11.18 ; off-sheet DIODE
EEV_A: IC11.4 ; off-sheet EEV_A
EEV_B: IC11.5 ; off-sheet EEV_B
EEV_C: IC11.11 ; off-sheet EEV_C
EEV_D: IC11.12 ; off-sheet EEV_D
EMG0: IC11.41 ; off-sheet EMG0
EMG1: IC11.55 ; off-sheet EMG1
EXHAUST: IC11.26 ; off-sheet EXHAUST
FWV: IC11.45 ; off-sheet FWV
HVMOS: IC11.28 ; off-sheet HVMOS
IAC_AD: IC11.29 ; off-sheet IAC_AD
IGBT: IC11.17 ; off-sheet IGBT
LED1: IC11.33 ; off-sheet LED1
LED2: IC11.34 ; off-sheet LED2
LED3: IC11.10 ; off-sheet LED3
LED4: IC11.7 ; off-sheet LED4
NetC99_1: C99.1 FB2.2 IC11.24
NetFB1_1: FB1.1 R82.2
OUTPIPE: IC11.25 ; off-sheet OUTPIPE
OUTROOM: IC11.27 ; off-sheet OUTROOM
PFC_FO: IC11.8 ; off-sheet PFC_FO
PFC_PWM: IC11.6 ; off-sheet PFC_PWM
PTC: IC11.20 ; off-sheet PTC
PWM_UH0: IC11.35 ; off-sheet PWM_UH0
PWM_UH1: IC11.49 ; off-sheet PWM_UH1
PWM_UL0: IC11.36 ; off-sheet PWM_UL0
PWM_UL1: IC11.50 ; off-sheet PWM_UL1
PWM_VH0: IC11.37 ; off-sheet PWM_VH0
PWM_VH1: IC11.51 ; off-sheet PWM_VH1
PWM_VL0: IC11.38 ; off-sheet PWM_VL0
PWM_VL1: IC11.52 ; off-sheet PWM_VL1
PWM_WH0: IC11.39 ; off-sheet PWM_WH0
PWM_WH1: IC11.53 ; off-sheet PWM_WH1
PWM_WL0: IC11.40 ; off-sheet PWM_WL0
PWM_WL1: IC11.54 ; off-sheet PWM_WL1
RESET: C38.2 IC11.63 R81.1 ; off-sheet RESET
RXD0: IC11.32 ; off-sheet RXD0
RXD2: IC11.2 ; off-sheet RXD2
SCLK: CN2.3 IC11.48
SDIN: CN2.2 IC11.47
SWCLK: CN1.3 IC11.64
SWDIO: CN1.4 IC11.1
SYNC: CN2.4 IC11.46
TXD0: IC11.31 ; off-sheet TXD0
TXD2: IC11.3 ; off-sheet TXD2
VAC_AD: IC11.30 ; off-sheet VAC_AD
VDC_AD: IC11.19 ; off-sheet VDC_AD
VOUT3: C42.2 C43.2 IC11.57
VOUT15: C40.2 C41.2 IC11.58
X1: C44.1 IC11.61 Y1.1
X2: C45.1 IC11.62 Y1.2

Not connected (* = marked no-connect by the designer): CN1 2

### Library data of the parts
C38 = C: OriginalSymbolOrigin: (2540,7620); VAL3: AC0805KKX7R9BB105
C39 C40 C42 C64 C65 C98 C99 = C: as C22 on sheet 2
C41 = C: OriginalSymbolOrigin: (2540,7620); COMP: AC0805KKX7R8BB475
C43 = C: OriginalSymbolOrigin: (2540,7620); VAL3: AC0805KKX7R8BB475
C44 = C: OriginalSymbolOrigin: (2540,7620); VAL3: AC0805JRNPO9BN200
C45 = C: OriginalSymbolOrigin: (2540,7620); COMP: AC0805JRNPO9BN200
CN1 CN2 = CN5: OriginalSymbolOrigin: (2540,22860)
EC18 = EC: SAVEAREA0: -1432,-1528,20311,14389; SAVECOUNT: 53; TIME: 15:02:55; UPDATEUSER: w20165dm; UPDATETIME: 16:35:05; OriginalSymbolOrigin: (2540,10160); VAL3: ESY476M035AE3AA; COMP: 35V47UF_6.3X7
FB1 = FL08A: SAVEAREA0: -112,-1299,15373,8886; TIME: 08:53:27; UPDATEUSER: kishi-s; UPDATETIME: 15:03:21; SAVECOUNT: 4; OriginalSymbolOrigin: (5080,5080); VAL2: 3A; VAL1: 0ohm
FB2 = FL08A_Dup1: SAVEAREA0: -112,-1299,15373,8886; TIME: 08:53:27; UPDATEUSER: kishi-s; UPDATETIME: 15:03:21; SAVECOUNT: 4; OriginalSymbolOrigin: (5080,5080); VAL2: 3A; VAL1: 0ohm
IC11 = TMPM4KLFYAUG: SAVEAREA0: -81909,-1350,188872,133365; TIME: 14:58:35; UPDATEUSER: w20165dm; UPDATETIME: 11:11:19; SAVECOUNT: 16; OriginalSymbolOrigin: (7620,129540); USERCOMPTEXT3: TOSHIBA
R81 = R: OriginalSymbolOrigin: (5080,5080); VAL2: 125mW; VAL3: AC0805FR-0710KL; COMP: AC08005FR_0710KL
R82 = R: OriginalSymbolOrigin: (5080,5080); VAL2: 125mW; VAL3: AC0805FR-074R7L; COMP: AC0805FR_074R7L
R108 = R: OriginalSymbolOrigin: (5080,5080); VAL3: AC0805FR_0710KL; VAL2: 125mW; COMP: AC08005FR_0710KL
TP33 = TP_Dup1: TIME: 16:12:21; UPDATEUSER: fukuda-y; UPDATETIME: 16:18:11; SAVECOUNT: 2; SAVEAREA0: -242,-92,12810,7836; OriginalSymbolOrigin: (0,7620); VAL3: ZXD; COMPCOMMENT: AVDD
U?#3 = WAKU_DEF100: PLOTTIME: HH:MM; SAVEAREA0: -45080,-4508,463680,304612; TIME: 18:05:21; UPDATEUSER: sptcae13; UPDATETIME: 08:19:30; SAVECOUNT: 8; OriginalSymbolOrigin: (10160,284480)
Y1 = X: SAVEAREA0: -5556,-184,20536,15665; TIME: 10:12:32; UPDATEUSER: fukuda-y; SAVECOUNT: 1; OriginalSymbolOrigin: (0,10160); VAL3: NX5032GA_10MHZ_STD_CSK_7

## Sheet 4.SchDoc
size 420 x 297 mm
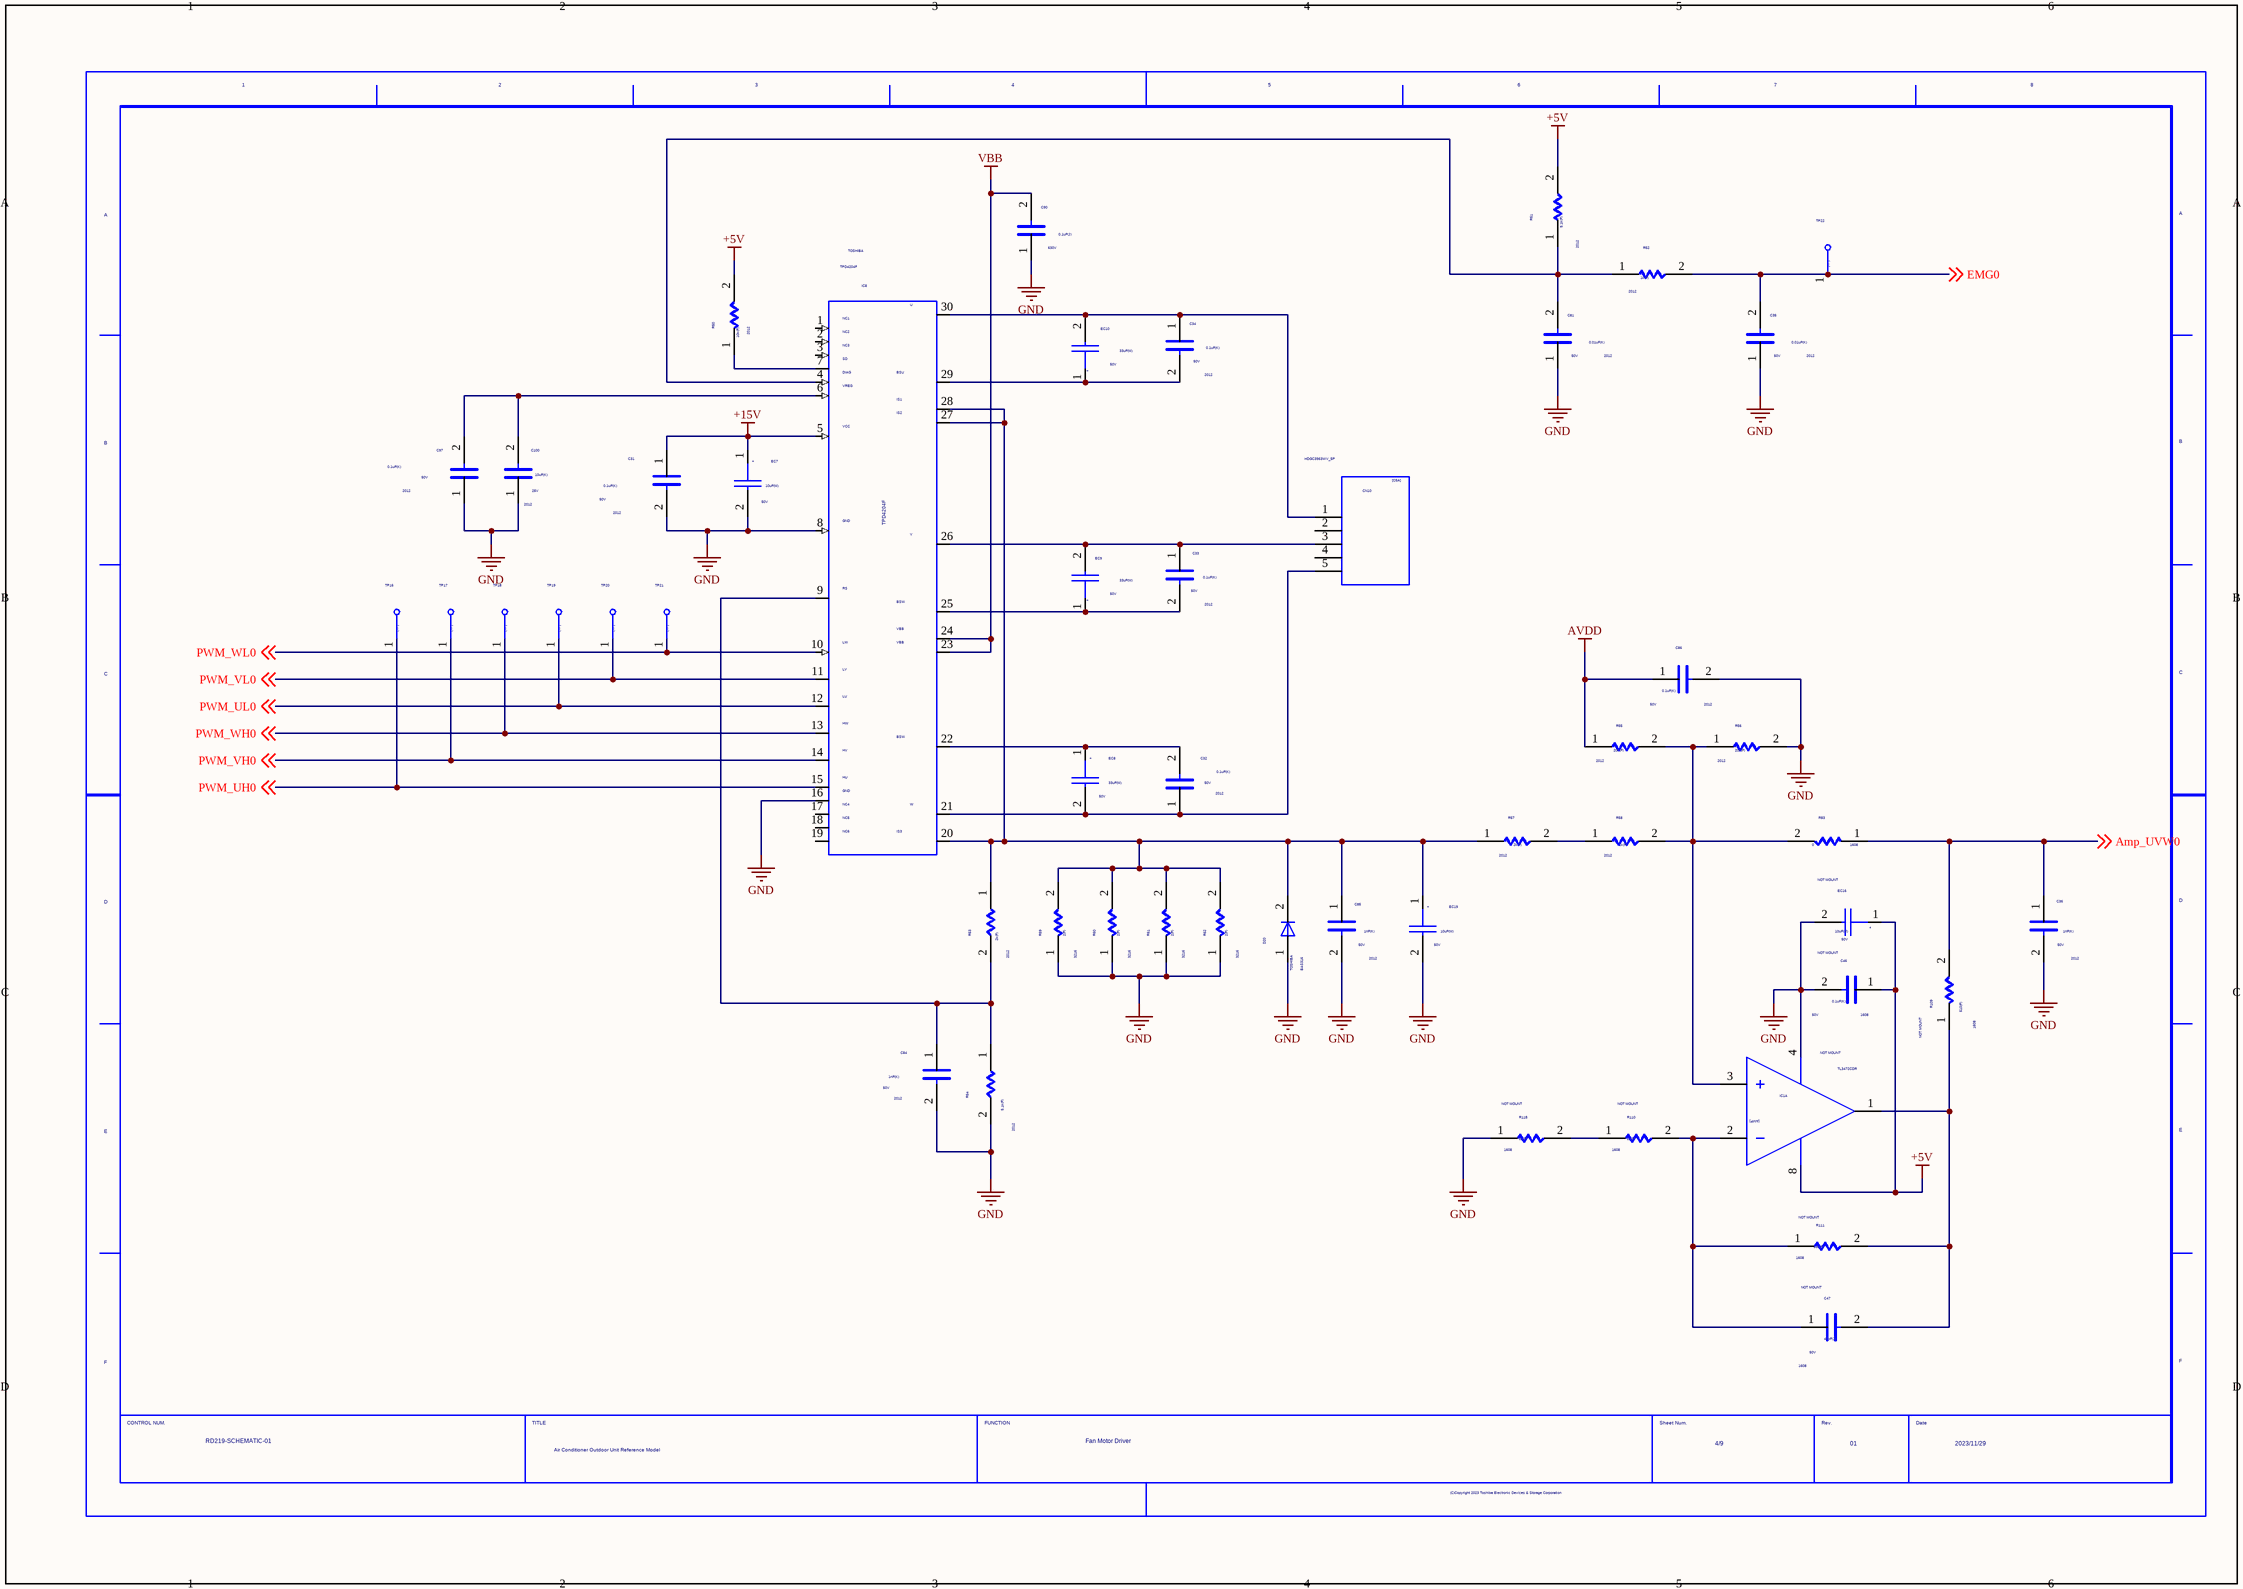
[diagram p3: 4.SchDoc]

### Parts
(Parts that share a designator on the sheet are numbered #1, #2 ... from top to bottom, then left to right.)
C31  VAL2: 50V  SIZECODESMD: 2012  VAL1: 0.1uF(K)  (hidden comment: C)
C32  VAL2: 50V  SIZECODESMD: 2012  VAL1: 0.1uF(K)  (hidden comment: C)
C33  VAL2: 50V  SIZECODESMD: 2012  VAL1: 0.1uF(K)  (hidden comment: C)
C34  VAL2: 50V  SIZECODESMD: 2012  VAL1: 0.1uF(K)  (hidden comment: C)
C35  VAL2: 50V  SIZECODESMD: 2012  VAL1: 0.01uF(K)  (hidden comment: C)
C36  VAL2: 50V  SIZECODESMD: 2012  VAL1: 1nF(K)  (hidden comment: C)
C46  NOTMOUNT: NOT MOUNT  VAL1: 0.1uF(K)  VAL2: 50V  SIZECODESMD: 1608  (hidden comment: C)
C47  NOTMOUNT: NOT MOUNT  VAL1: 47pF(J)  VAL2: 50V  SIZECODESMD: 1608  (hidden comment: C)
C81  VAL2: 50V  SIZECODESMD: 2012  VAL1: 0.01uF(K)  (hidden comment: C)
C84  VAL2: 50V  SIZECODESMD: 2012  VAL1: 1nF(K)  (hidden comment: C)
C85  VAL2: 50V  SIZECODESMD: 2012  VAL1: 1nF(K)  (hidden comment: C)
C86  VAL2: 50V  SIZECODESMD: 2012  VAL1: 0.1uF(K)  (hidden comment: C)
C90  VAL2: 630V  VAL1: 0.1uF(J)  (hidden comment: C)
C97  VAL2: 50V  SIZECODESMD: 2012  VAL1: 0.1uF(K)  (hidden comment: C)
C100  VAL2: 25V  SIZECODESMD: 2012  VAL1: 10uF(K)  (hidden comment: C)
CN10  VAL3: HDGC3963WV_5P  (hidden comment: C5A)
D20  USERCOMPTEXT3: TOSHIBA  VAL3: BAS316  (hidden comment: D_CUSTOM)
EC7  VAL2: 50V  VAL1: 10uF(M)  (hidden comment: EC)
EC8  VAL2: 50V  VAL1: 33uF(M)  (hidden comment: EC)
EC9  VAL2: 50V  VAL1: 33uF(M)  (hidden comment: EC)
EC10  VAL2: 50V  VAL1: 33uF(M)  (hidden comment: EC)
EC16  NOTMOUNT: NOT MOUNT  VAL2: 50V  VAL1: 10uF(M)  (hidden comment: EC)
EC19  VAL2: 50V  VAL1: 10uF(M)  (hidden comment: EC)
IC1  NOTMOUNT: NOT MOUNT  VAL3: TL3472CDR  (hidden comment: AMP_1)  (part A of 2)
IC8  USERCOMPTEXT3: TOSHIBA  (hidden comment: TPD4204F)
R50  SIZECODESMD: 2012  VAL1: 10k(F)  (hidden comment: R)
R51  SIZECODESMD: 2012  VAL1: 5.1k(F)  (hidden comment: R)
R52  SIZECODESMD: 2012  VAL1: 1k(F)  (hidden comment: R)
R53  SIZECODESMD: 2012  VAL1: 2k(F)  (hidden comment: R)
R54  SIZECODESMD: 2012  VAL1: 5.1k(F)  (hidden comment: R)
R55  SIZECODESMD: 2012  VAL1: 20k(F)  (hidden comment: R)
R56  SIZECODESMD: 2012  VAL1: 20k(F)  (hidden comment: R)
R57  SIZECODESMD: 2012  VAL1: 2k(F)  (hidden comment: R)
R58  SIZECODESMD: 2012  VAL1: 2k(F)  (hidden comment: R)
R59  SIZECODESMD: 3216  VAL1: 2(F)  (hidden comment: R)
R60  SIZECODESMD: 3216  VAL1: 2(F)  (hidden comment: R)
R61  SIZECODESMD: 3216  VAL1: 2(F)  (hidden comment: R)
R62  SIZECODESMD: 3216  VAL1: 2(F)  (hidden comment: R)
R83  SIZECODESMD: 1608  VAL1: 0  (hidden comment: R)
R109  NOTMOUNT: NOT MOUNT  SIZECODESMD: 1608  VAL1: 510(F)  (hidden comment: R)
R110  NOTMOUNT: NOT MOUNT  SIZECODESMD: 1608  VAL1: 2k(F)  (hidden comment: R)
R111  NOTMOUNT: NOT MOUNT  SIZECODESMD: 1608  VAL1: 10k(F)  (hidden comment: R)
R115  NOTMOUNT: NOT MOUNT  SIZECODESMD: 1608  VAL1: 2k(F)  (hidden comment: R)
TP16  TP  (value not drawn)
TP17  TP  (value not drawn)
TP18  TP  (value not drawn)
TP19  TP  (value not drawn)
TP20  TP  (value not drawn)
TP21  TP  (value not drawn)
TP22  TP  (value not drawn)
U?#4  DATE: 2023/11/29  FUNCTION: Fan Motor Driver  TITLE: Air Conditioner Outdoor Unit / Reference Model  DRAWINGNUMBER: RD219-SCHEMATIC-01  SHEETNUMBER: 4/9  REVISION: 01  (hidden comment: WAKU_DEF100)

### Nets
+5V: C46.1 EC16.1 IC1.8 R50.2 R51.2
+15V: C31.1 EC7.1 IC8.5
AVDD: C86.1 R55.1
GND: C31.2 C35.1 C36.2 C46.2 C81.1 C84.2 C85.2 C86.2 C90.1 C97.1 C100.1 D20.1 EC7.2 EC16.2 EC19.2 IC1.4 IC8.8 IC8.16 R54.2 R56.2 R59.1 R60.1 R61.1 R62.1 R115.1
VBB: C90.2 IC8.23 IC8.24
Amp_UVW0: C36.1 R83.1 R109.2 ; off-sheet Amp_UVW0
EMG0: C35.2 R52.2 TP22.1 ; off-sheet EMG0
NetC32_1: C32.1 CN10.5 EC8.2 IC8.21
NetC32_2: C32.2 EC8.1 IC8.22
NetC33_1: C33.1 CN10.3 EC9.2 IC8.26
NetC33_2: C33.2 EC9.1 IC8.25
NetC34_1: C34.1 CN10.1 EC10.2 IC8.30
NetC34_2: C34.2 EC10.1 IC8.29
NetC47_1: C47.1 IC1.2 R110.2 R111.1
NetC47_2: C47.2 IC1.1 R109.1 R111.2
NetC81_2: C81.2 IC8.4 R51.1 R52.1
NetC84_1: C84.1 IC8.9 R53.2 R54.1
NetC85_1: C85.1 D20.2 EC19.1 IC8.20 IC8.27 IC8.28 R53.1 R57.1 R59.2 R60.2 R61.2 R62.2
NetC97_2: C97.2 C100.2 IC8.6
NetIC1_3: IC1.3 R55.2 R56.1 R58.2 R83.2
NetIC8_7: IC8.7 R50.1
NetR57_2: R57.2 R58.1
NetR110_1: R110.1 R115.2
PWM_UH0: IC8.15 TP16.1 ; off-sheet PWM_UH0
PWM_UL0: IC8.12 TP19.1 ; off-sheet PWM_UL0
PWM_VH0: IC8.14 TP17.1 ; off-sheet PWM_VH0
PWM_VL0: IC8.11 TP20.1 ; off-sheet PWM_VL0
PWM_WH0: IC8.13 TP18.1 ; off-sheet PWM_WH0
PWM_WL0: IC8.10 TP21.1 ; off-sheet PWM_WL0

Not connected (* = marked no-connect by the designer): CN10 2 4; IC8 1 2 3 17 18 19

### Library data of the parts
C31-C34 C86 C97 = C: OriginalSymbolOrigin: (2540,7620); COMP: AC0805KRX7R9BB104
C35 C81 = C: OriginalSymbolOrigin: (2540,7620); COMP: AC0805KRX7R9BB103
C36 C84 C85 = C: OriginalSymbolOrigin: (2540,7620); COMP: AC0805KRX7R9BB102
C46 = C: OriginalSymbolOrigin: (2540,7620); COMP: AC0603KRX7R9BB104
C47 = C: OriginalSymbolOrigin: (2540,7620); VAL3: AC0603JRNPO9BN470
C90 = C: OriginalSymbolOrigin: (2540,7620); COMP: CBB22_104J630V
C100 = C: OriginalSymbolOrigin: (2540,7620); COMP: AC0805KKX5R8BB106
CN10 = C5A: SAVEAREA0: -9193,-269,29123,23485; TIME: 08:44:29; UPDATEUSER: fukuda-y; UPDATETIME: 10:06:49; SAVECOUNT: 4; OriginalSymbolOrigin: (2540,20320); COMPCOMMENT: VH3.96/5P
D20 = D_CUSTOM: as D1 on sheet 1
EC7 = EC: SAVEAREA0: -1432,-1528,20311,14389; SAVECOUNT: 53; TIME: 15:02:55; UPDATEUSER: w20165dm; UPDATETIME: 16:35:05; OriginalSymbolOrigin: (2540,10160); VAL3: ESS106M050AE2AA
EC8-EC10 = EC: SAVEAREA0: -1432,-1528,20311,14389; SAVECOUNT: 53; TIME: 15:02:55; UPDATEUSER: w20165dm; UPDATETIME: 16:35:05; OriginalSymbolOrigin: (2540,10160); VAL3: ESH336M050AE3AA
EC16 EC19 = EC: SAVEAREA0: -1432,-1528,20311,14389; SAVECOUNT: 53; TIME: 15:02:55; UPDATEUSER: w20165dm; UPDATETIME: 16:35:05; OriginalSymbolOrigin: (2540,10160); VAL3: ESS106M050AE2AA; COMP: 50V10UF_5X11
IC1 = AMP_1: SAVEAREA0: -6226,-235,36343,20943; TIME: 17:09:52; UPDATEUSER: w20165dm; SAVECOUNT: 1; OriginalSymbolOrigin: (5080,20320); CaptureCellPackProp: AMP_1A; FUNCN: IC1_1
IC8 = TPD4204F: TIME: 16:32:01; UPDATEUSER: sptcae13; UPDATETIME: 10:27:40; SAVECOUNT: 16; SAVEAREA0: -113524,-1329,136787,112726; OriginalSymbolOrigin: (2540,106680)
R50 = R: OriginalSymbolOrigin: (5080,5080); COMP: AC08005FR_0710KL; VAL3: AC0805FR-0710KL; VAL2: 125mW
R51 R54 = R: OriginalSymbolOrigin: (5080,5080); COMP: AC0805FR_075K1L; VAL3: AC0805FR-075K1L; VAL2: 125mW
R52 = R: OriginalSymbolOrigin: (5080,5080); COMP: AC0805FR_071KL; VAL3: AC0805FR-071KL; VAL2: 125mW
R53 R57 R58 = R: OriginalSymbolOrigin: (5080,5080); COMP: AC0805FR_072KL; VAL3: AC0805FR-072KL; VAL2: 125mW
R55 R56 = R: OriginalSymbolOrigin: (5080,5080); COMP: AC0805FR_0720KL; VAL3: AC0805FR-0720KL; VAL2: 125mW
R59-R62 = R: OriginalSymbolOrigin: (5080,5080); COMP: AC1206FR_072RL; VAL3: AC1206FR-072RL; VAL2: 250mW
R83 = R: OriginalSymbolOrigin: (5080,5080); COMP: AC0603FR_070RL; VAL2: 100mW
R109 = R: OriginalSymbolOrigin: (5080,5080); COMP: AC0603FR_07510RL; VAL2: 100mW
R110 R115 = R: OriginalSymbolOrigin: (5080,5080); COMP: AC0603FR_072KL; VAL2: 100mW
R111 = R: OriginalSymbolOrigin: (5080,5080); COMP: AC0603FR_0710KL; VAL2: 100mW
TP16 = TP_Dup1: TIME: 16:12:21; UPDATEUSER: fukuda-y; UPDATETIME: 16:18:11; SAVECOUNT: 2; SAVEAREA0: -242,-92,12810,7836; OriginalSymbolOrigin: (0,7620); COMPCOMMENT: UH0; VAL3: ZXD
TP17 = TP_Dup1: TIME: 16:12:21; UPDATEUSER: fukuda-y; UPDATETIME: 16:18:11; SAVECOUNT: 2; SAVEAREA0: -242,-92,12810,7836; OriginalSymbolOrigin: (0,7620); COMPCOMMENT: VH0; VAL3: ZXD
TP18 = TP_Dup1: TIME: 16:12:21; UPDATEUSER: fukuda-y; UPDATETIME: 16:18:11; SAVECOUNT: 2; SAVEAREA0: -242,-92,12810,7836; OriginalSymbolOrigin: (0,7620); COMPCOMMENT: WH0; VAL3: ZXD
TP19 = TP_Dup1: TIME: 16:12:21; UPDATEUSER: fukuda-y; UPDATETIME: 16:18:11; SAVECOUNT: 2; SAVEAREA0: -242,-92,12810,7836; OriginalSymbolOrigin: (0,7620); COMPCOMMENT: UL0; VAL3: ZXD
TP20 = TP_Dup1: TIME: 16:12:21; UPDATEUSER: fukuda-y; UPDATETIME: 16:18:11; SAVECOUNT: 2; SAVEAREA0: -242,-92,12810,7836; OriginalSymbolOrigin: (0,7620); COMPCOMMENT: VL0; VAL3: ZXD
TP21 = TP_Dup1: TIME: 16:12:21; UPDATEUSER: fukuda-y; UPDATETIME: 16:18:11; SAVECOUNT: 2; SAVEAREA0: -242,-92,12810,7836; OriginalSymbolOrigin: (0,7620); COMPCOMMENT: WL0; VAL3: ZXD
TP22 = TP_Dup1: TIME: 16:12:21; UPDATEUSER: fukuda-y; UPDATETIME: 16:18:11; SAVECOUNT: 2; SAVEAREA0: -242,-92,12810,7836; OriginalSymbolOrigin: (0,7620); COMPCOMMENT: EMG0; VAL3: ZXD
U?#4 = WAKU_DEF100: PLOTTIME: HH:MM; SAVEAREA0: -45080,-4508,463680,304612; TIME: 18:02:41; UPDATEUSER: sptcae13; UPDATETIME: 08:19:30; SAVECOUNT: 8; OriginalSymbolOrigin: (10160,284480)

## Sheet 5.SchDoc
size 420 x 297 mm
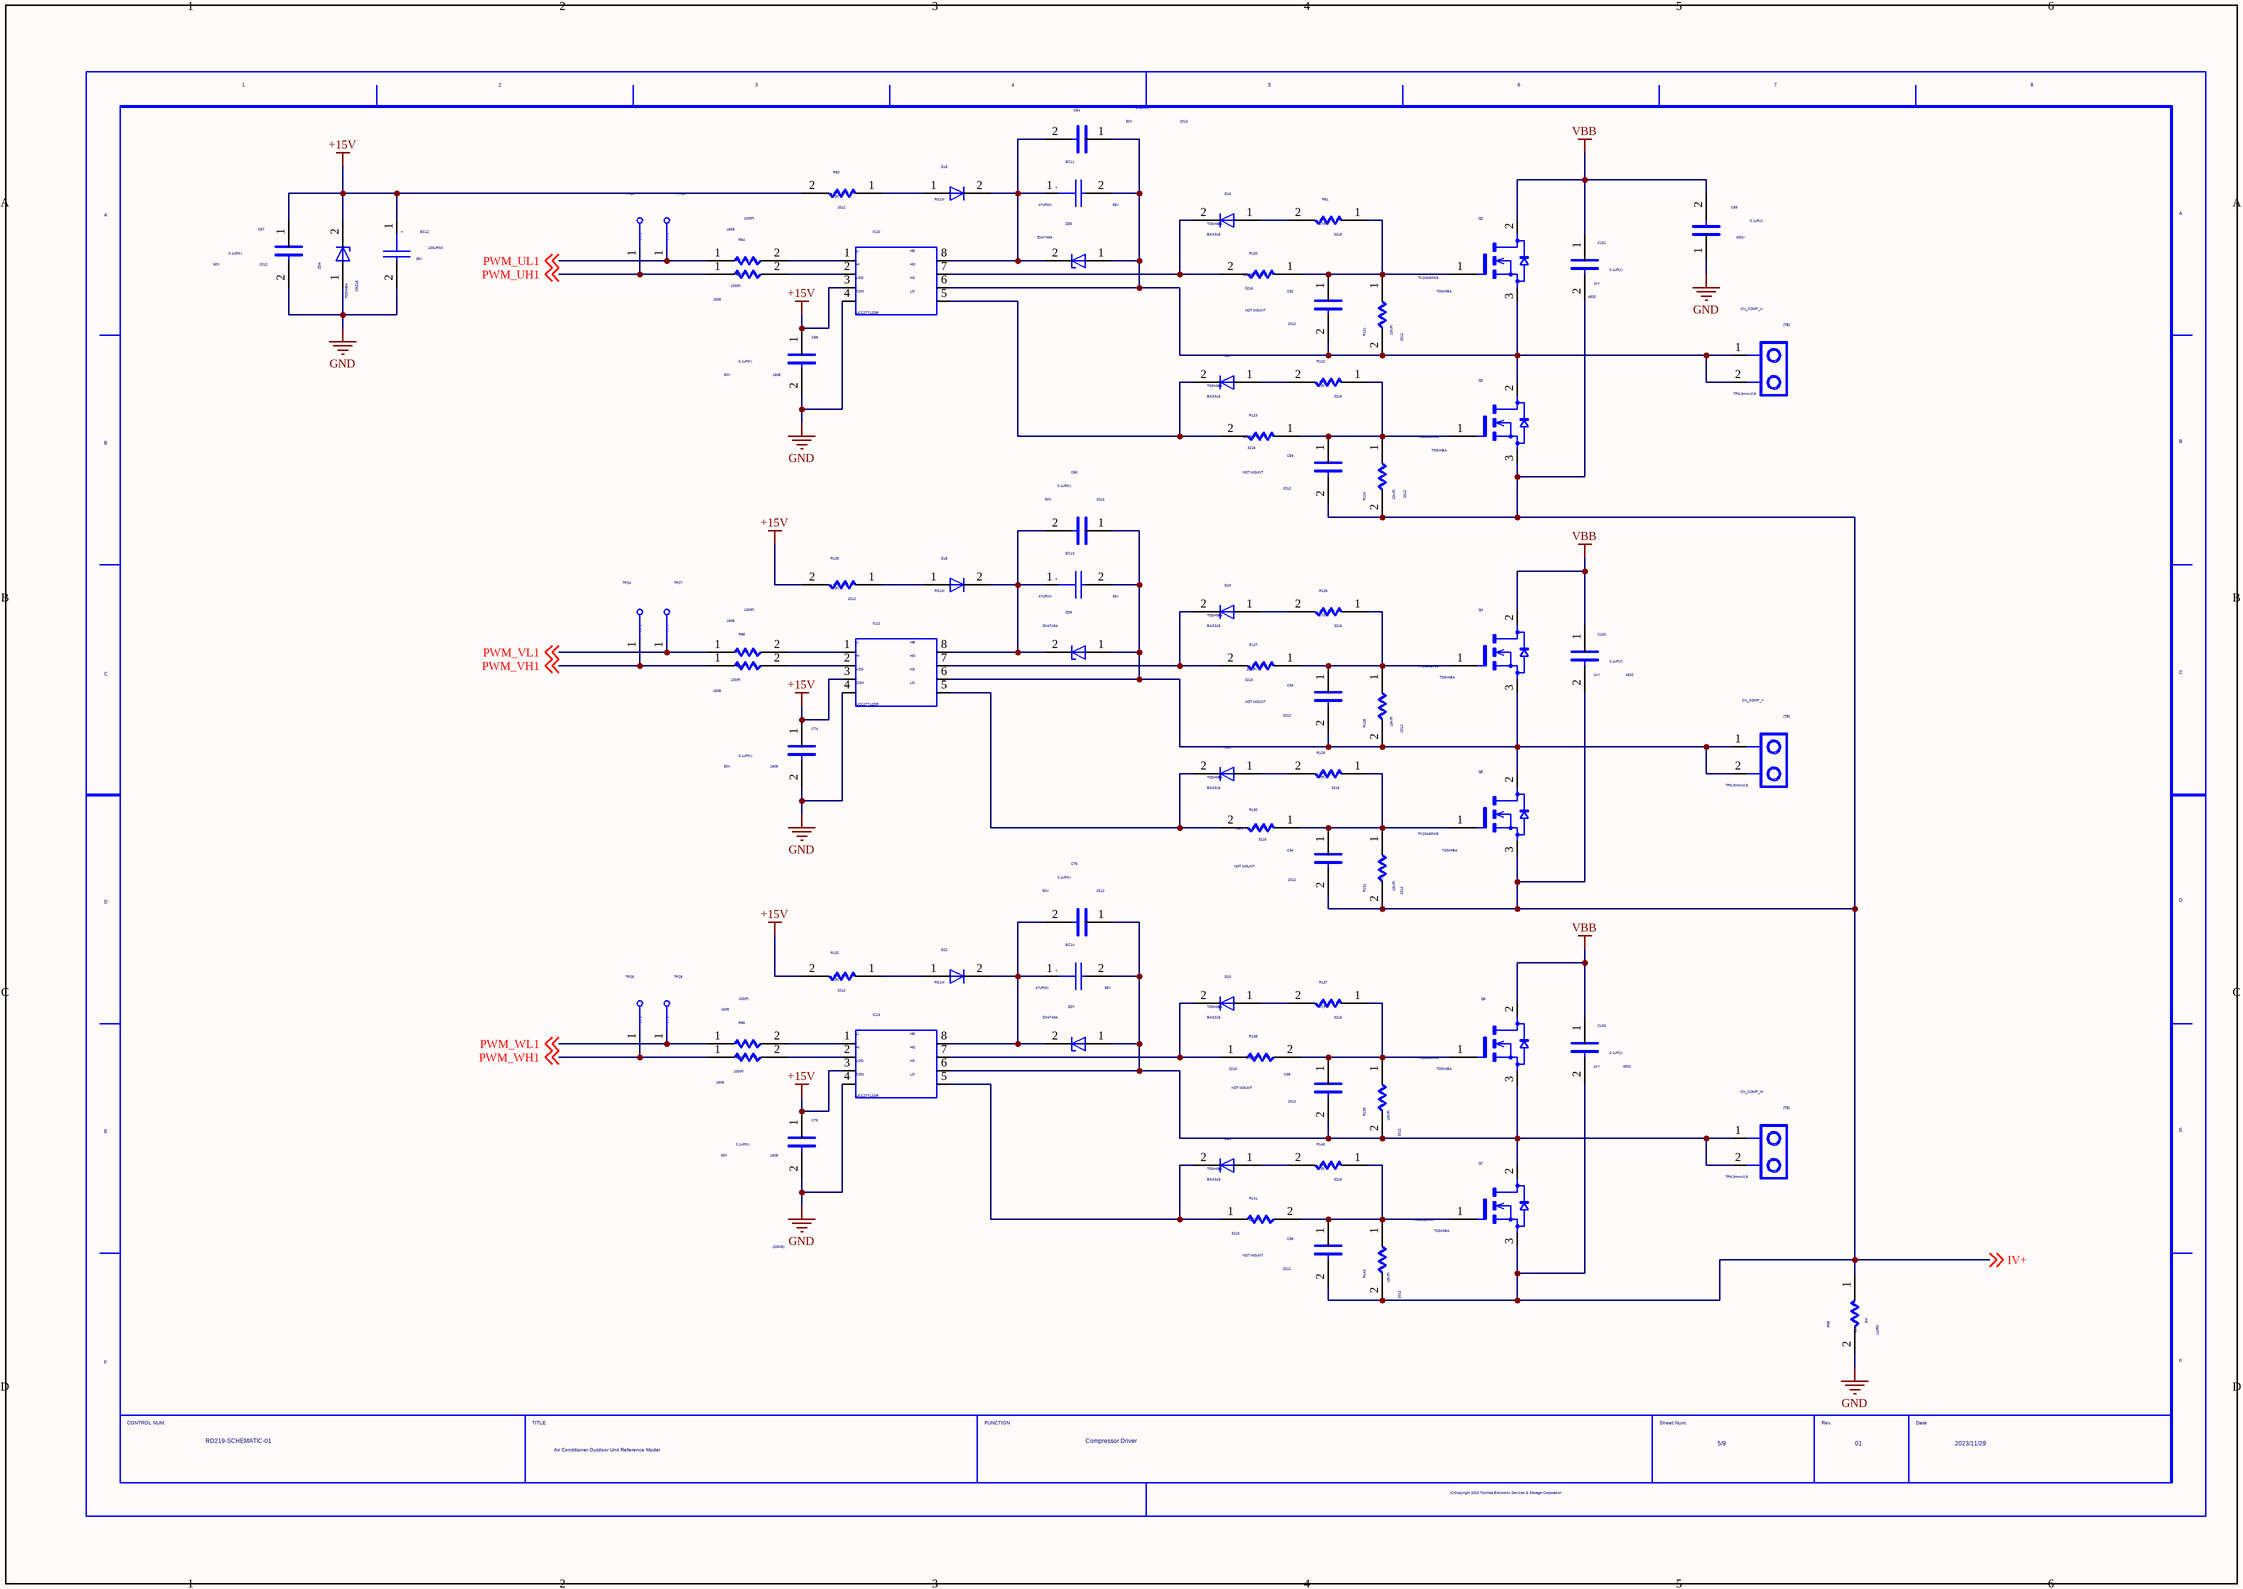
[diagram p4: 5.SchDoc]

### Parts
(Parts that share a designator on the sheet are numbered #1, #2 ... from top to bottom, then left to right.)
C54  VAL2: 50V  SIZECODESMD: 2012  VAL1: 0.1uF(K)  (hidden comment: C)
C55  VAL2: 630V  VAL1: 0.1uF(J)  (hidden comment: C)
C57  SIZECODESMD: 2012  VAL2: 50V  VAL1: 0.1uF(K)  (hidden comment: C)
C58  VAL2: 50V  SIZECODESMD: 1608  VAL1: 0.1uF(K)  (hidden comment: C)
C59  SIZECODESMD: 2012  NOTMOUNT: NOT MOUNT  (hidden comment: C)
C60  VAL2: 50V  SIZECODESMD: 2012  VAL1: 0.1uF(K)  (hidden comment: C)
C74  VAL2: 50V  SIZECODESMD: 1608  VAL1: 0.1uF(K)  (hidden comment: C)
C75  VAL2: 50V  SIZECODESMD: 2012  VAL1: 0.1uF(K)  (hidden comment: C)
C76  COMPCOMMENT: (SGND)  VAL2: 50V  SIZECODESMD: 1608  VAL1: 0.1uF(K)  (hidden comment: C)
C92  NOTMOUNT: NOT MOUNT  SIZECODESMD: 2012  (hidden comment: C)
C93  NOTMOUNT: NOT MOUNT  SIZECODESMD: 2012  (hidden comment: C)
C94  SIZECODESMD: 2012  NOTMOUNT: NOT MOUNT  (hidden comment: C)
C95  NOTMOUNT: NOT MOUNT  SIZECODESMD: 2012  (hidden comment: C)
C96  SIZECODESMD: 2012  NOTMOUNT: NOT MOUNT  (hidden comment: C)
C101  VAL2: 1kV  SIZECODESMD: 4532  VAL1: 0.1uF(J)  (hidden comment: C)
C102  VAL2: 1kV  SIZECODESMD: 4532  VAL1: 0.1uF(J)  (hidden comment: C)
C103  VAL2: 1kV  SIZECODESMD: 4532  VAL1: 0.1uF(J)  (hidden comment: C)
CN_COMP_U  COMPCOMMENT: TP6.3mmx0.8  (hidden comment: TB2A)
CN_COMP_V  COMPCOMMENT: TP6.3mmx0.8  (hidden comment: TB2A)
CN_COMP_W  COMPCOMMENT: TP6.3mmx0.8  (hidden comment: TB2A)
D15  VAL3: RS1M  (hidden comment: D_CUSTOM)
D16  USERCOMPTEXT3: TOSHIBA  VAL3: BAS316  (hidden comment: D_CUSTOM)
D17  USERCOMPTEXT3: TOSHIBA  VAL3: BAS316  (hidden comment: D_CUSTOM)
D18  VAL3: RS1M  (hidden comment: D_CUSTOM)
D19  USERCOMPTEXT3: TOSHIBA  VAL3: BAS316  (hidden comment: D_CUSTOM)
D21  USERCOMPTEXT3: TOSHIBA  VAL3: BAS316  (hidden comment: D_CUSTOM)
D22  VAL3: RS1M  (hidden comment: D_CUSTOM)
D23  USERCOMPTEXT3: TOSHIBA  VAL3: BAS316  (hidden comment: D_CUSTOM)
D24  USERCOMPTEXT3: TOSHIBA  VAL3: BAS316  (hidden comment: D_CUSTOM)
EC11  VAL2: 35V  VAL1: 47uF(M)  (hidden comment: EC)
EC12  VAL2: 35V  VAL1: 100uF(M)  (hidden comment: EC)
EC13  VAL2: 35V  VAL1: 47uF(M)  (hidden comment: EC)
EC14  VAL2: 35V  VAL1: 47uF(M)  (hidden comment: EC)
IC10  VAL3: UCC27712DR  (hidden comment: UCC27712)
IC12  VAL3: UCC27712DR  (hidden comment: UCC27712)
IC13  VAL3: UCC27712DR  (hidden comment: UCC27712)
Q2  USERCOMPTEXT3: TOSHIBA  (hidden comment: TK20A60W5)
Q3  USERCOMPTEXT3: TOSHIBA  (hidden comment: TK20A60W5)
Q4  USERCOMPTEXT3: TOSHIBA  (hidden comment: TK20A60W5)
Q5  USERCOMPTEXT3: TOSHIBA  (hidden comment: TK20A60W5)
Q6  USERCOMPTEXT3: TOSHIBA  (hidden comment: TK20A60W5)
Q7  USERCOMPTEXT3: TOSHIBA  (hidden comment: TK20A60W5)
R84  SIZECODESMD: 1608  VAL1: 100(F)  (hidden comment: R)
R85  SIZECODESMD: 1608  VAL1: 100(F)  (hidden comment: R)
R86  SIZECODESMD: 1608  VAL1: 100(F)  (hidden comment: R)
R87  SIZECODESMD: 1608  VAL1: 100(F)  (hidden comment: R)
R88  SIZECODESMD: 1608  VAL1: 100(F)  (hidden comment: R)
R89  SIZECODESMD: 1608  VAL1: 100(F)  (hidden comment: R)
R90  SIZECODESMD: 2012  VAL1: 47(F)  (hidden comment: R)
R91  SIZECODESMD: 3216  VAL1: 47(F)  (hidden comment: R)
R95  VAL2: 5W  SIZECODESMD: 11050  VAL1: 10m  (hidden comment: R)
R120  SIZECODESMD: 3216  VAL1: 200(F)  (hidden comment: R)
R121  SIZECODESMD: 2012  VAL1: 10k(F)  (hidden comment: R)
R122  SIZECODESMD: 3216  VAL1: 47(F)  (hidden comment: R)
R123  SIZECODESMD: 3216  VAL1: 200(F)  (hidden comment: R)
R124  SIZECODESMD: 2012  VAL1: 10k(F)  (hidden comment: R)
R125  SIZECODESMD: 2012  VAL1: 47(F)  (hidden comment: R)
R126  SIZECODESMD: 3216  VAL1: 47(F)  (hidden comment: R)
R127  SIZECODESMD: 3216  VAL1: 200(F)  (hidden comment: R)
R128  SIZECODESMD: 2012  VAL1: 10k(F)  (hidden comment: R)
R129  SIZECODESMD: 3216  VAL1: 47(F)  (hidden comment: R)
R130  SIZECODESMD: 3216  VAL1: 200(F)  (hidden comment: R)
R131  SIZECODESMD: 2012  VAL1: 10k(F)  (hidden comment: R)
R132  SIZECODESMD: 2012  VAL1: 47(F)  (hidden comment: R)
R137  SIZECODESMD: 3216  VAL1: 47(F)  (hidden comment: R)
R138  SIZECODESMD: 3216  VAL1: 200(F)  (hidden comment: R)
R139  SIZECODESMD: 2012  VAL1: 10k(F)  (hidden comment: R)
R140  SIZECODESMD: 3216  VAL1: 47(F)  (hidden comment: R)
R141  SIZECODESMD: 3216  VAL1: 200(J)  (hidden comment: R)
R143  SIZECODESMD: 2012  VAL1: 10k(F)  (hidden comment: R)
TP23  TP  (value not drawn)
TP24  TP  (value not drawn)
TP25  TP  (value not drawn)
TP26  TP  (value not drawn)
TP27  TP  (value not drawn)
TP28  TP  (value not drawn)
U?#5  DATE: 2023/11/29  FUNCTION: Compressor Driver  TITLE: Air Conditioner Outdoor Unit / Reference Model  DRAWINGNUMBER: RD219-SCHEMATIC-01  SHEETNUMBER: 5/9  REVISION: 01  (hidden comment: WAKU_DEF100)
ZD4  USERCOMPTEXT3: TOSHIBA  VAL3: CRZ18  (hidden comment: ZD_CUSTOM)
ZD5  VAL3: ZM4749A  (hidden comment: ZD_CUSTOM)
ZD6  VAL3: ZM4749A  (hidden comment: ZD_CUSTOM)
ZD7  VAL3: ZM4749A  (hidden comment: ZD_CUSTOM)

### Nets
+15V: C57.1 C58.1 C74.1 C76.1 EC12.1 IC10.3 IC12.3 IC13.3 R90.2 R125.2 R132.2 ZD4.2
GND: C55.1 C57.2 C58.2 C74.2 C76.2 EC12.2 IC10.4 IC12.4 IC13.4 R95.2 ZD4.1
VBB: C55.2 C101.1 C102.1 C103.1 Q2.2 Q4.2 Q6.2
IV+: C59.2 C94.2 C96.2 C101.2 C102.2 C103.2 Q3.3 Q5.3 Q7.3 R95.1 R124.2 R131.2 R143.2 ; off-sheet IV+
NetC54_1: C54.1 C92.2 CN_COMP_U.1 CN_COMP_U.2 EC11.2 IC10.6 Q2.3 Q3.2 R121.2 ZD5.1
NetC54_2: C54.2 D15.2 EC11.1 IC10.8 ZD5.2
NetC59_1: C59.1 Q3.1 R122.1 R123.1 R124.1
NetC60_1: C60.1 C93.2 CN_COMP_V.1 CN_COMP_V.2 EC13.2 IC12.6 Q4.3 Q5.2 R128.2 ZD6.1
NetC60_2: C60.2 D18.2 EC13.1 IC12.8 ZD6.2
NetC75_1: C75.1 C95.2 CN_COMP_W.1 CN_COMP_W.2 EC14.2 IC13.6 Q6.3 Q7.2 R139.2 ZD7.1
NetC75_2: C75.2 D22.2 EC14.1 IC13.8 ZD7.2
NetC92_1: C92.1 Q2.1 R91.1 R120.1 R121.1
NetC93_1: C93.1 Q4.1 R126.1 R127.1 R128.1
NetC94_1: C94.1 Q5.1 R129.1 R130.1 R131.1
NetC95_1: C95.1 Q6.1 R137.1 R138.2 R139.1
NetC96_1: C96.1 Q7.1 R140.1 R141.2 R143.1
NetD15_1: D15.1 R90.1
NetD16_1: D16.1 R91.2
NetD16_2: D16.2 IC10.7 R120.2
NetD17_1: D17.1 R122.2
NetD17_2: D17.2 IC10.5 R123.2
NetD18_1: D18.1 R125.1
NetD19_1: D19.1 R126.2
NetD19_2: D19.2 IC12.7 R127.2
NetD21_1: D21.1 R129.2
NetD21_2: D21.2 IC12.5 R130.2
NetD22_1: D22.1 R132.1
NetD23_1: D23.1 R137.2
NetD23_2: D23.2 IC13.7 R138.1
NetD24_1: D24.1 R140.2
NetD24_2: D24.2 IC13.5 R141.1
NetIC10_1: IC10.1 R84.2
NetIC10_2: IC10.2 R87.2
NetIC12_1: IC12.1 R85.2
NetIC12_2: IC12.2 R88.2
NetIC13_1: IC13.1 R86.2
NetIC13_2: IC13.2 R89.2
PWM_UH1: R87.1 TP23.1 ; off-sheet PWM_UH1
PWM_UL1: R84.1 TP26.1 ; off-sheet PWM_UL1
PWM_VH1: R88.1 TP24.1 ; off-sheet PWM_VH1
PWM_VL1: R85.1 TP27.1 ; off-sheet PWM_VL1
PWM_WH1: R89.1 TP25.1 ; off-sheet PWM_WH1
PWM_WL1: R86.1 TP28.1 ; off-sheet PWM_WL1

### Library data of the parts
C54 C60 C75 = C: as C31 on sheet 4
C55 = C: as C90 on sheet 4
C57 = C: as C22 on sheet 2
C58 C74 C76 = C: as C46 on sheet 4
C59 C92-C96 = C: OriginalSymbolOrigin: (2540,7620); COMP: SMT_0805_C
C101-C103 = C: OriginalSymbolOrigin: (2540,7620); COMP: C1812C104JDRACTU
CN_COMP_U CN_COMP_V CN_COMP_W = TB2A: SAVEAREA0: -6249,-369,19007,18120; TIME: 11:16:32; UPDATEUSER: w20165dm; SAVECOUNT: 1; OriginalSymbolOrigin: (2540,12700); VAL3: DJ6110-6.3x0.8; COMP: TP
D15-D19 D21-D24 = D_CUSTOM: as D1 on sheet 1
EC11 EC13 EC14 = EC: as EC15 on sheet 1
EC12 = EC: SAVEAREA0: -1432,-1528,20311,14389; SAVECOUNT: 53; TIME: 15:02:55; UPDATEUSER: w20165dm; UPDATETIME: 16:35:05; OriginalSymbolOrigin: (2540,10160); VAL3: CS1V101M_CRE77
IC10 IC12 IC13 = UCC27712: COMPTYPERIPPER: Y; TIME: 09:28:59; UPDATEUSER: sptcae13; UPDATETIME: 09:18:42; SAVECOUNT: 4; SAVEAREA0: -15749,-25534,36467,12691; OriginalSymbolOrigin: (2540,0)
Q2-Q7 = TK20A60W5: SAVECOUNT: 12; SAVEAREA0: -8472,-176,23454,15707; TIME: 13:50:47; UPDATEUSER: w20165dm; OriginalSymbolOrigin: (5080,12700)
R84-R89 = R: OriginalSymbolOrigin: (5080,5080); COMP: AC0603FR_07100RL; VAL2: 100mW
R90 R125 R132 = R: OriginalSymbolOrigin: (5080,5080); COMP: AC0805FR_0747RL; VAL2: 125mW
R91 R122 R126 R129 R137 R140 = R: OriginalSymbolOrigin: (5080,5080); COMP: AC1206FR_0747RL; VAL2: 250mW
R95 = R: OriginalSymbolOrigin: (5080,5080); COMP: FCSL110R010FER
R120 R123 R127 R130 R138 R141 = R: OriginalSymbolOrigin: (5080,5080); COMP: AC1206FR_07200RL; VAL2: 250mW
R121 R124 R128 R131 R139 R143 = R: OriginalSymbolOrigin: (5080,5080); COMP: AC08005FR_0710KL; VAL3: AC0805FR_0710KL; VAL2: 125mW
TP23 = TP_Dup1: TIME: 16:12:21; UPDATEUSER: fukuda-y; UPDATETIME: 16:18:11; SAVECOUNT: 2; SAVEAREA0: -242,-92,12810,7836; OriginalSymbolOrigin: (0,7620); COMPCOMMENT: UH1; VAL3: ZXD
TP24 = TP_Dup1: TIME: 16:12:21; UPDATEUSER: fukuda-y; UPDATETIME: 16:18:11; SAVECOUNT: 2; SAVEAREA0: -242,-92,12810,7836; OriginalSymbolOrigin: (0,7620); COMPCOMMENT: VH1; VAL3: ZXD
TP25 = TP_Dup1: TIME: 16:12:21; UPDATEUSER: fukuda-y; UPDATETIME: 16:18:11; SAVECOUNT: 2; SAVEAREA0: -242,-92,12810,7836; OriginalSymbolOrigin: (0,7620); COMPCOMMENT: WH1; VAL3: ZXD
TP26 = TP_Dup1: TIME: 16:12:21; UPDATEUSER: fukuda-y; UPDATETIME: 16:18:11; SAVECOUNT: 2; SAVEAREA0: -242,-92,12810,7836; OriginalSymbolOrigin: (0,7620); COMPCOMMENT: UL1; VAL3: ZXD
TP27 = TP_Dup1: TIME: 16:12:21; UPDATEUSER: fukuda-y; UPDATETIME: 16:18:11; SAVECOUNT: 2; SAVEAREA0: -242,-92,12810,7836; OriginalSymbolOrigin: (0,7620); COMPCOMMENT: VL1; VAL3: ZXD
TP28 = TP_Dup1: TIME: 16:12:21; UPDATEUSER: fukuda-y; UPDATETIME: 16:18:11; SAVECOUNT: 2; SAVEAREA0: -242,-92,12810,7836; OriginalSymbolOrigin: (0,7620); COMPCOMMENT: WL1; VAL3: ZXD
U?#5 = WAKU_DEF100: PLOTTIME: HH:MM; SAVEAREA0: -45080,-4508,463680,304612; TIME: 10:14:29; UPDATEUSER: sptcae13; UPDATETIME: 08:19:30; SAVECOUNT: 8; OriginalSymbolOrigin: (10160,284480)
ZD4 = ZD_CUSTOM: SAVEAREA0: -4071,-115,16804,10270; TIME: 09:43:08; UPDATEUSER: w20165dm; UPDATETIME: 16:32:57; SAVECOUNT: 4; OriginalSymbolOrigin: (5080,5080)
ZD5-ZD7 = ZD_CUSTOM: SAVEAREA0: -4071,-115,16804,10270; TIME: 09:43:08; UPDATEUSER: w20165dm; UPDATETIME: 16:32:57; SAVECOUNT: 4; OriginalSymbolOrigin: (5080,5080); VAL2: 1W; VAL1: 24V

## Sheet 6.SchDoc
size 420 x 297 mm
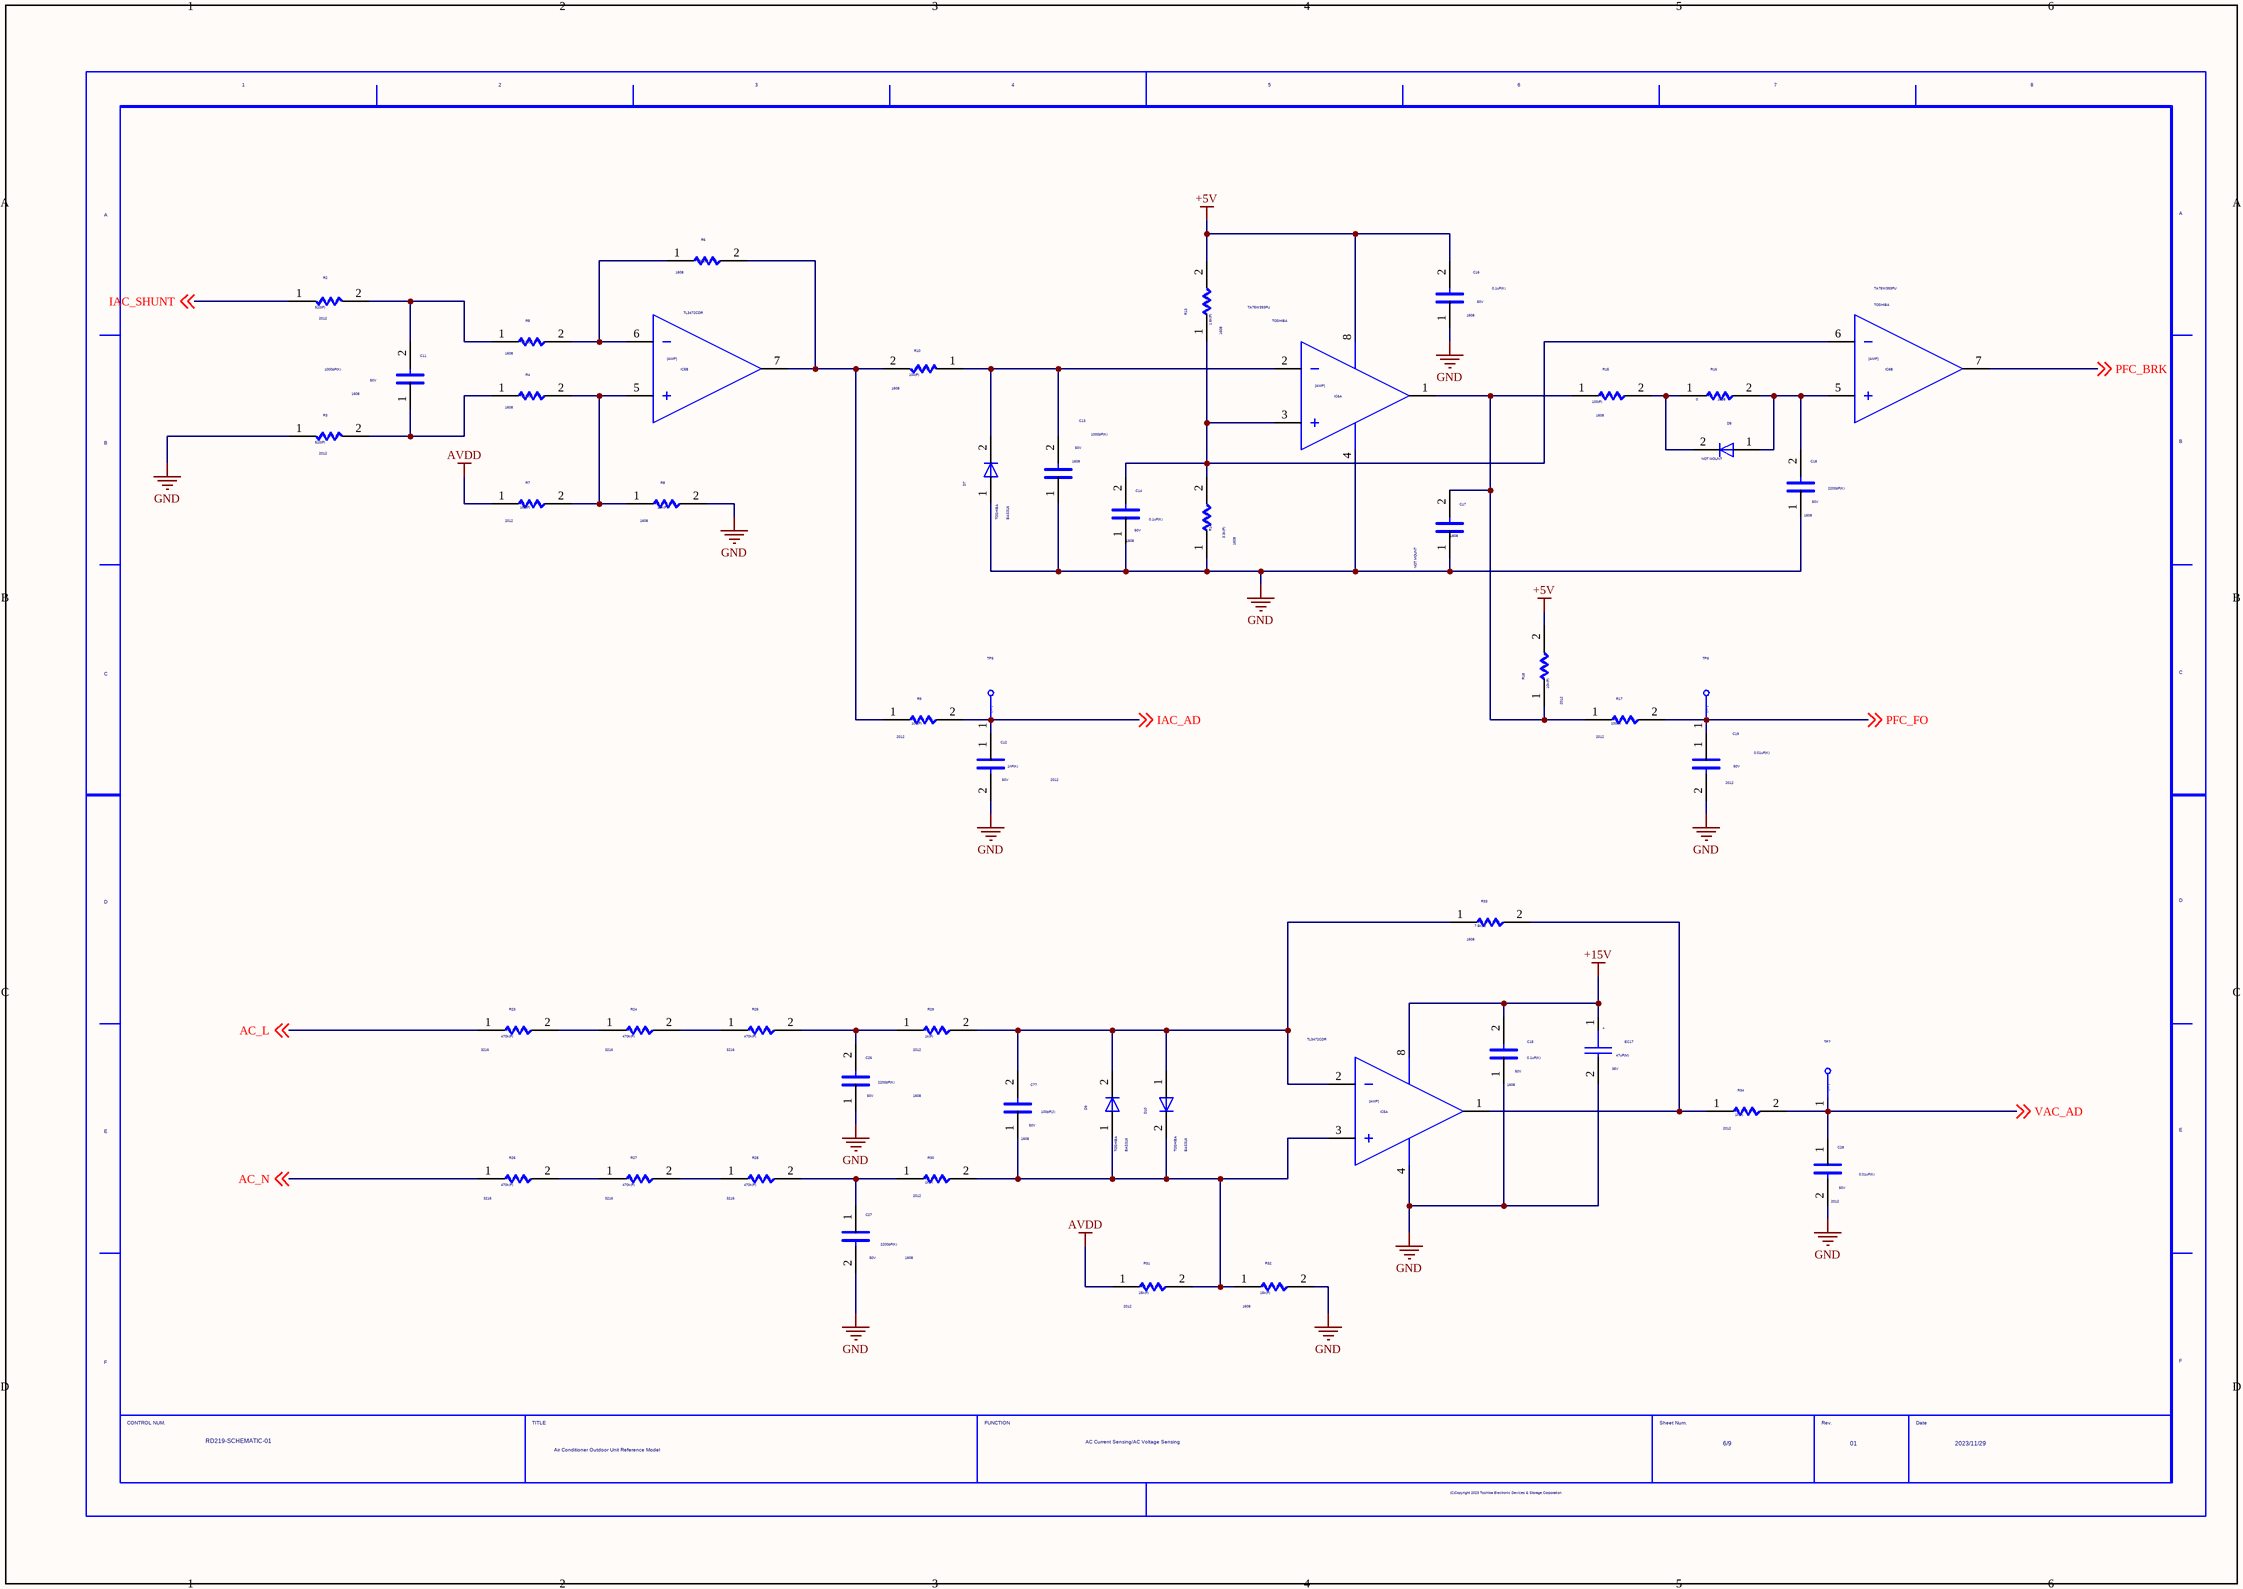
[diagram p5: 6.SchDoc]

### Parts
(Parts that share a designator on the sheet are numbered #1, #2 ... from top to bottom, then left to right.)
C11  SIZECODESMD: 1608  VAL2: 50V  VAL1: 1000pF(K)  (hidden comment: C)
C12  SIZECODESMD: 2012  VAL2: 50V  VAL1: 1nF(K)  (hidden comment: C)
C13  SIZECODESMD: 1608  VAL2: 50V  VAL1: 1000pF(K)  (hidden comment: C)
C14  SIZECODESMD: 1608  VAL2: 50V  VAL1: 0.1uF(K)  (hidden comment: C)
C15  SIZECODESMD: 1608  VAL2: 50V  VAL1: 0.1uF(K)  (hidden comment: C)
C16  SIZECODESMD: 1608  VAL2: 50V  VAL1: 0.1uF(K)  (hidden comment: C)
C17  SIZECODESMD: 1608  NOTMOUNT: NOT MOUNT  (hidden comment: C)
C18  SIZECODESMD: 1608  VAL2: 50V  VAL1: 2200pF(K)  (hidden comment: C)
C19  SIZECODESMD: 2012  VAL2: 50V  VAL1: 0.01uF(K)  (hidden comment: C)
C26  SIZECODESMD: 1608  VAL2: 50V  VAL1: 2200pF(K)  (hidden comment: C)
C27  SIZECODESMD: 1608  VAL2: 50V  VAL1: 2200pF(K)  (hidden comment: C)
C28  SIZECODESMD: 2012  VAL2: 50V  VAL1: 0.01uF(K)  (hidden comment: C)
C77  SIZECODESMD: 1608  VAL2: 50V  VAL1: 100pF(J)  (hidden comment: C)
D7  USERCOMPTEXT3: TOSHIBA  VAL3: BAS316  (hidden comment: D_CUSTOM)
D8  NOTMOUNT: NOT MOUNT  (hidden comment: D_CUSTOM)
D9  USERCOMPTEXT3: TOSHIBA  VAL3: BAS316  (hidden comment: D_CUSTOM)
D10  USERCOMPTEXT3: TOSHIBA  VAL3: BAS316  (hidden comment: D_CUSTOM)
EC17  VAL2: 35V  VAL1: 47uF(M)  (hidden comment: EC)
IC5  VAL1: TL3472CDR  (hidden comment: AMP_1)  (parts A,B of 2)
IC6  USERCOMPTEXT3: TOSHIBA  VAL1: TA75W393FU  (hidden comment: AMP_1)  (parts A,B of 2)
R2  SIZECODESMD: 2012  VAL1: 510(F)  (hidden comment: R)
R3  SIZECODESMD: 2012  VAL1: 510(F)  (hidden comment: R)
R4  VAL1: 510(F)  SIZECODESMD: 1608  (hidden comment: R)
R5  VAL1: 510(F)  SIZECODESMD: 1608  (hidden comment: R)
R6  VAL1: 7.5k(F)  SIZECODESMD: 1608  (hidden comment: R)
R7  VAL1: 15k(F)  SIZECODESMD: 2012  (hidden comment: R)
R8  VAL1: 15k(F)  SIZECODESMD: 1608  (hidden comment: R)
R9  VAL1: 100(F)  SIZECODESMD: 2012  (hidden comment: R)
R10  VAL1: 100(F)  SIZECODESMD: 1608  (hidden comment: R)
R13  VAL1: 1.5k(F)  SIZECODESMD: 1608  (hidden comment: R)
R14  VAL1: 3.3k(F)  SIZECODESMD: 1608  (hidden comment: R)
R15  SIZECODESMD: 1608  VAL1: 100(F)  (hidden comment: R)
R16  SIZECODESMD: 1608  VAL1: 0  (hidden comment: R)
R17  SIZECODESMD: 2012  VAL1: 100(F)  (hidden comment: R)
R18  SIZECODESMD: 2012  VAL1: 10k(F)  (hidden comment: R)
R23  SIZECODESMD: 3216  VAL1: 470k(F)  (hidden comment: R)
R24  SIZECODESMD: 3216  VAL1: 470k(F)  (hidden comment: R)
R25  SIZECODESMD: 3216  VAL1: 470k(F)  (hidden comment: R)
R26  SIZECODESMD: 3216  VAL1: 470k(F)  (hidden comment: R)
R27  SIZECODESMD: 3216  VAL1: 470k(F)  (hidden comment: R)
R28  SIZECODESMD: 3216  VAL1: 470k(F)  (hidden comment: R)
R29  SIZECODESMD: 2012  VAL1: 1k(F)  (hidden comment: R)
R30  SIZECODESMD: 2012  VAL1: 1k(F)  (hidden comment: R)
R31  SIZECODESMD: 2012  VAL1: 15k(F)  (hidden comment: R)
R32  SIZECODESMD: 1608  VAL1: 15k(F)  (hidden comment: R)
R33  SIZECODESMD: 1608  VAL1: 7.5k(F)  (hidden comment: R)
R34  SIZECODESMD: 2012  VAL1: 1k(F)  (hidden comment: R)
TP5  TP  (value not drawn)
TP6  TP  (value not drawn)
TP7  TP  (value not drawn)
U?#6  DATE: 2023/11/29  TITLE: Air Conditioner Outdoor Unit / Reference Model  SHEETNUMBER: 6/9  DRAWINGNUMBER: RD219-SCHEMATIC-01  FUNCTION: AC Current Sensing/AC Voltage Sensing  REVISION: 01  (hidden comment: WAKU_DEF100)

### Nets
+5V: C16.2 IC6.8 R13.2 R18.2
+15V: C15.2 EC17.1 IC5.8
AVDD: R7.1 R31.1
GND: C12.2 C13.1 C14.1 C15.1 C16.1 C17.1 C18.1 C19.2 C26.1 C27.2 C28.2 D7.1 EC17.2 IC5.4 IC6.4 R3.1 R8.2 R14.1 R32.2
AC_L: R23.1 ; off-sheet AC_L
AC_N: R26.1 ; off-sheet AC_N
IAC_AD: C12.1 R9.2 TP5.1 ; off-sheet IAC_AD
IAC_SHUNT: R2.1 ; off-sheet IAC_SHUNT
NetC11_1: C11.1 R3.2 R4.1
NetC11_2: C11.2 R2.2 R5.1
NetC13_2: C13.2 D7.2 IC6.2 R10.1
NetC14_2: C14.2 IC6.3 IC6.6 R13.1 R14.2
NetC17_2: C17.2 IC6.1 R15.1 R17.1 R18.1
NetC18_2: C18.2 D8.1 IC6.5 R16.2
NetC26_2: C26.2 R25.2 R29.1
NetC27_1: C27.1 R28.2 R30.1
NetC77_1: C77.1 D9.1 D10.2 IC5.3 R30.2 R31.2 R32.1
NetC77_2: C77.2 D9.2 D10.1 IC5.2 R29.2 R33.1
NetD8_2: D8.2 R15.2 R16.1
NetIC5_1: IC5.1 R33.2 R34.1
NetIC5_5: IC5.5 R4.2 R7.2 R8.1
NetIC5_6: IC5.6 R5.2 R6.1
NetIC5_7: IC5.7 R6.2 R9.1 R10.2
NetR23_2: R23.2 R24.1
NetR24_2: R24.2 R25.1
NetR26_2: R26.2 R27.1
NetR27_2: R27.2 R28.1
PFC_BRK: IC6.7 ; off-sheet PFC_BRK
PFC_FO: C19.1 R17.2 TP6.1 ; off-sheet PFC_FO
VAC_AD: C28.1 R34.2 TP7.1 ; off-sheet VAC_AD

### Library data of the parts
C11 C13 = C_Dup1: OriginalSymbolOrigin: (2540,7620); VAL3: AC0603KRX7R9BB102
C12 = C_Dup1: as C9 on sheet 1
C14 = C_Dup1: OriginalSymbolOrigin: (2540,7620); COMP: AC0603KRX7R9BB104
C15 = C: OriginalSymbolOrigin: (2540,7620); VAL3: AC0603KRX7R9BB104
C16 = C_Dup1: OriginalSymbolOrigin: (2540,7620); VAL3: AC0603KRX7R9BB104
C17 = C_Dup1: OriginalSymbolOrigin: (2540,7620); COMP: SMT_0603_C
C18 = C_Dup1: OriginalSymbolOrigin: (2540,7620); VAL3: AC0603KRX7R9BB222
C19 = C_Dup1: OriginalSymbolOrigin: (2540,7620); COMP: AC0805KRX7R9BB103
C26 C27 = C: OriginalSymbolOrigin: (2540,7620); VAL3: AC0603KRX7R9BB222
C28 = C: OriginalSymbolOrigin: (2540,7620); VAL3: AC0805KRX7R9BB103
C77 = C: OriginalSymbolOrigin: (2540,7620); VAL3: AC0603JRNPO9BN101
D7 D9 D10 = D_CUSTOM: as D1 on sheet 1
D8 = D_CUSTOM: as D11 on sheet 1
EC17 = EC: as EC15 on sheet 1
IC5 = AMP_1: SAVEAREA0: -6226,-235,36343,20943; TIME: 17:09:52; UPDATEUSER: w20165dm; SAVECOUNT: 1; OriginalSymbolOrigin: (5080,20320); CaptureCellPackProp: AMP_1A; FUNCN: IC5_1
IC6 = AMP_1: SAVEAREA0: -6226,-235,36343,20943; TIME: 17:09:52; UPDATEUSER: w20165dm; SAVECOUNT: 1; OriginalSymbolOrigin: (5080,20320); CaptureCellPackProp: AMP_1A; FUNCN: IC6_1
R2 R3 = R_Dup1: OriginalSymbolOrigin: (5080,5080); COMP: AC0805FR_07510RL; VAL3: AC0805FR-07510RL; VAL2: 125mW
R4 R5 = R_Dup1: OriginalSymbolOrigin: (5080,5080); VAL3: AC0603FR-07510RL; COMP: AC0603FR_07510RL; VAL2: 100mW
R6 = R_Dup1: OriginalSymbolOrigin: (5080,5080); VAL3: AC0603FR-077K5L; COMP: AC0603FR_077K5L; VAL2: 100mW
R7 = R_Dup1: OriginalSymbolOrigin: (5080,5080); VAL3: AC0805FR-0715KL; COMP: AC0805FR_0715KL; VAL2: 125mW
R8 = R_Dup1: OriginalSymbolOrigin: (5080,5080); VAL3: AC0603FR-0715KL; COMP: AC0603FR_0715KL; VAL2: 100mW
R9 = R_Dup1: OriginalSymbolOrigin: (5080,5080); VAL3: AC0805FR-07100RL; COMP: AC0805FR_07100RL; VAL2: 125mW
R10 = R_Dup1: OriginalSymbolOrigin: (5080,5080); VAL3: AC0603FR-07100RL; COMP: AC0603FR_07100RL; VAL2: 100mW
R13 = R_Dup1: OriginalSymbolOrigin: (5080,5080); VAL3: AC0603FR-071K5L; COMP: AC0603FR_071K5L; VAL2: 100mW
R14 = R_Dup1: OriginalSymbolOrigin: (5080,5080); VAL3: AC0603FR-073K3L; COMP: AC0603FR_073K3L; VAL2: 100mW
R15 = R_Dup1: OriginalSymbolOrigin: (5080,5080); VAL2: 100mW; VAL3: AC0603FR-07100RL; COMP: AC0603FR_07100RL
R16 = R_Dup1: OriginalSymbolOrigin: (5080,5080); VAL2: 100mW; VAL3: AC0603FR-070RL; COMP: AC0603FR_070RL
R17 = R_Dup1: OriginalSymbolOrigin: (5080,5080); VAL2: 125mW; VAL3: AC0805FR-07100RL; COMP: AC0805FR_07100RL
R18 = R_Dup1: OriginalSymbolOrigin: (5080,5080); VAL2: 125mW; VAL3: AC0805FR-0710KL; COMP: AC0805FR_0710KL
R23 = R: OriginalSymbolOrigin: (5080,5080); VAL3: AC1206FR-07470KL; VAL2: 125mW; COMP: AC1206FR_07470KL
R24 = R: OriginalSymbolOrigin: (5080,5080); COMP: AC1206FR_07470KL; VAL3: AC1206FR-07470KL; VAL2: 250mW
R25 = R: OriginalSymbolOrigin: (5080,5080); VAL3: AC1206FR-07470KL; VAL2: 250mW; COMP: AC1206FR_07470KL
R26-R28 = R: OriginalSymbolOrigin: (5080,5080); VAL2: 250mW; VAL3: AC1206FR-07470KL; COMP: AC1206FR_07470KL
R29 R30 R34 = R: OriginalSymbolOrigin: (5080,5080); VAL2: 125mW; VAL3: AC0805FR-071KL; COMP: AC0805FR_071KL
R31 = R: OriginalSymbolOrigin: (5080,5080); VAL3: AC0805FR-0715KL; VAL2: 125mW; COMP: AC0805FR_0715KL
R32 = R: OriginalSymbolOrigin: (5080,5080); VAL3: AC0603FR-0715KL; VAL2: 100mW; COMP: AC0805FR_0715KL
R33 = R: OriginalSymbolOrigin: (5080,5080); VAL3: AC0603FR-077K5L; VAL2: 100mW; COMP: AC0603FR_077K5L
TP5 = TP: TIME: 16:12:21; UPDATEUSER: fukuda-y; UPDATETIME: 16:18:11; SAVECOUNT: 2; SAVEAREA0: -242,-92,12810,7836; OriginalSymbolOrigin: (0,7620); COMPCOMMENT: IAC_AD; VAL3: ZXD
TP6 = TP: TIME: 16:12:21; UPDATEUSER: fukuda-y; UPDATETIME: 16:18:11; SAVECOUNT: 2; SAVEAREA0: -242,-92,12810,7836; OriginalSymbolOrigin: (0,7620); VAL3: ZXD; COMPCOMMENT: PFC_FO
TP7 = TP_Dup1: TIME: 16:12:21; UPDATEUSER: fukuda-y; UPDATETIME: 16:18:11; SAVECOUNT: 2; SAVEAREA0: -242,-92,12810,7836; OriginalSymbolOrigin: (0,7620); VAL3: ZXD; COMPCOMMENT: VAC_AD
U?#6 = WAKU_DEF100: PLOTTIME: HH:MM; SAVEAREA0: -45080,-4508,463680,304612; TIME: 15:33:48; UPDATEUSER: sptcae13; UPDATETIME: 08:19:30; SAVECOUNT: 8; OriginalSymbolOrigin: (10160,284480)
